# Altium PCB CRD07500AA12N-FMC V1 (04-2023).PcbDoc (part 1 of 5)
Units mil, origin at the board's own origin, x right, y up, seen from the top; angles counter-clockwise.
Board outline 8000 x 8000 mil, 4 copper layers (Top Layer, Layer 1, Layer 2, Bottom Layer), stack 107.988 mil thick; 393 components, 213 nets, 1142 pads, 380 vias.
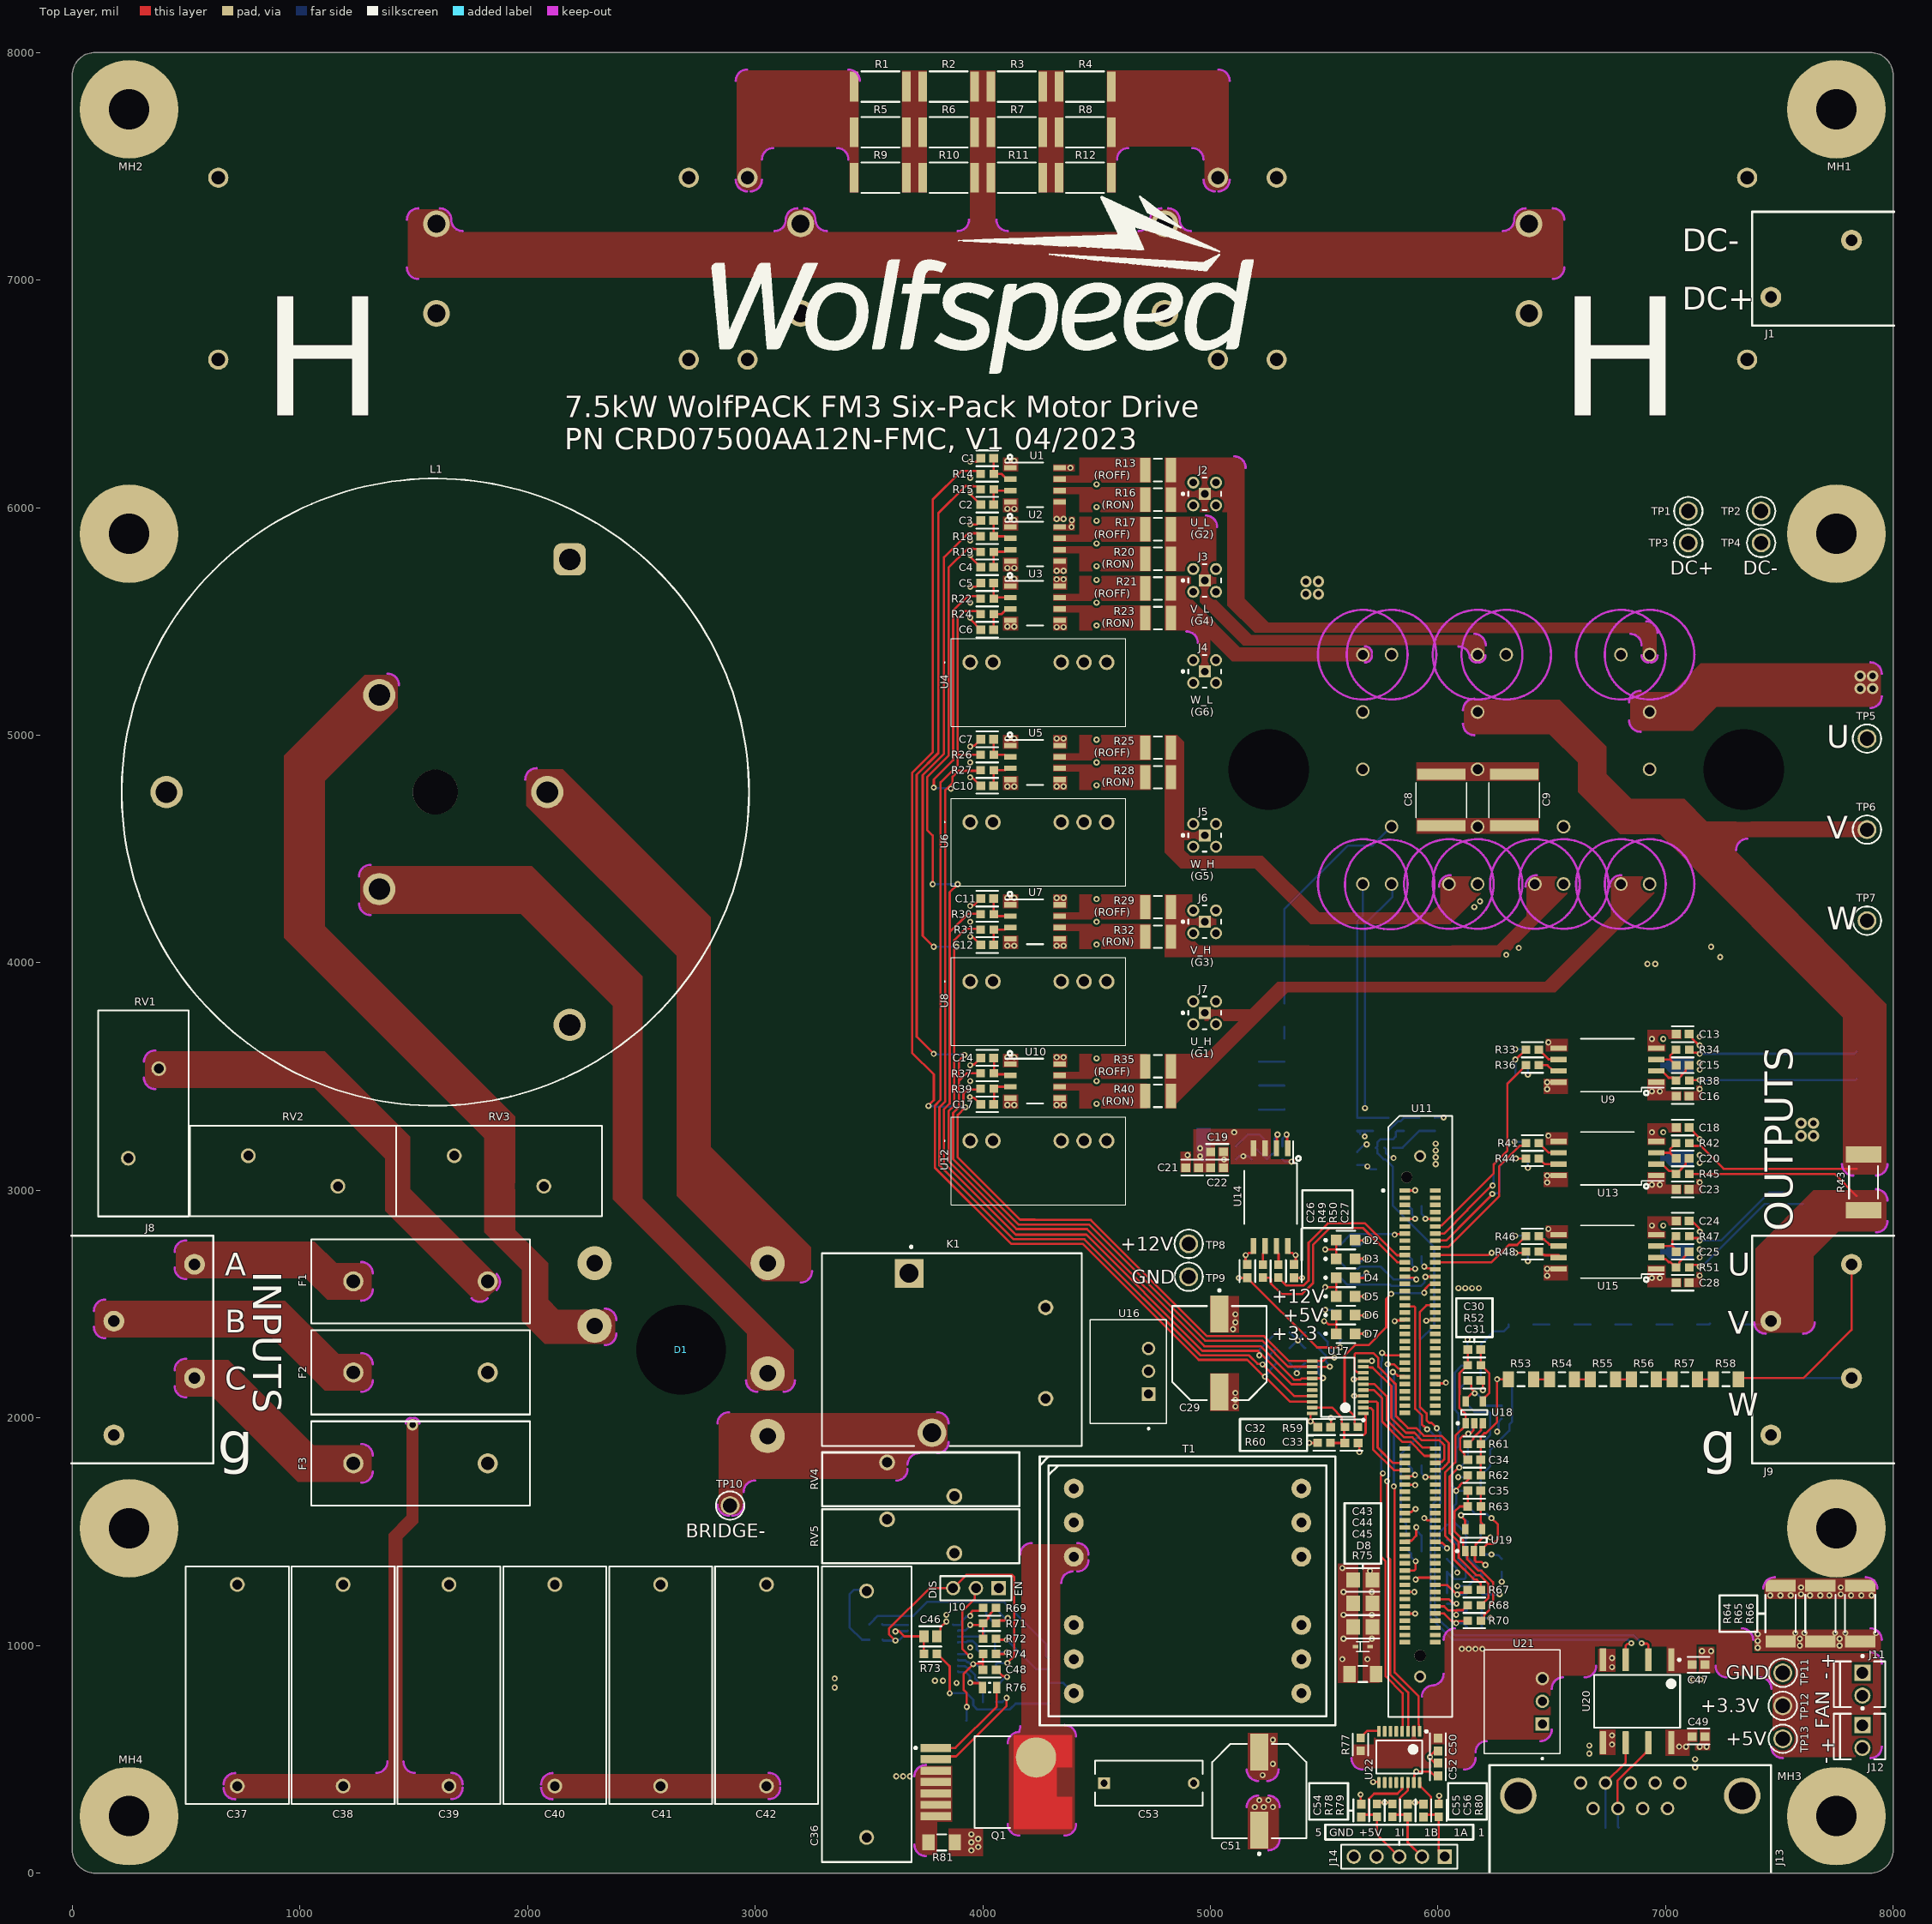
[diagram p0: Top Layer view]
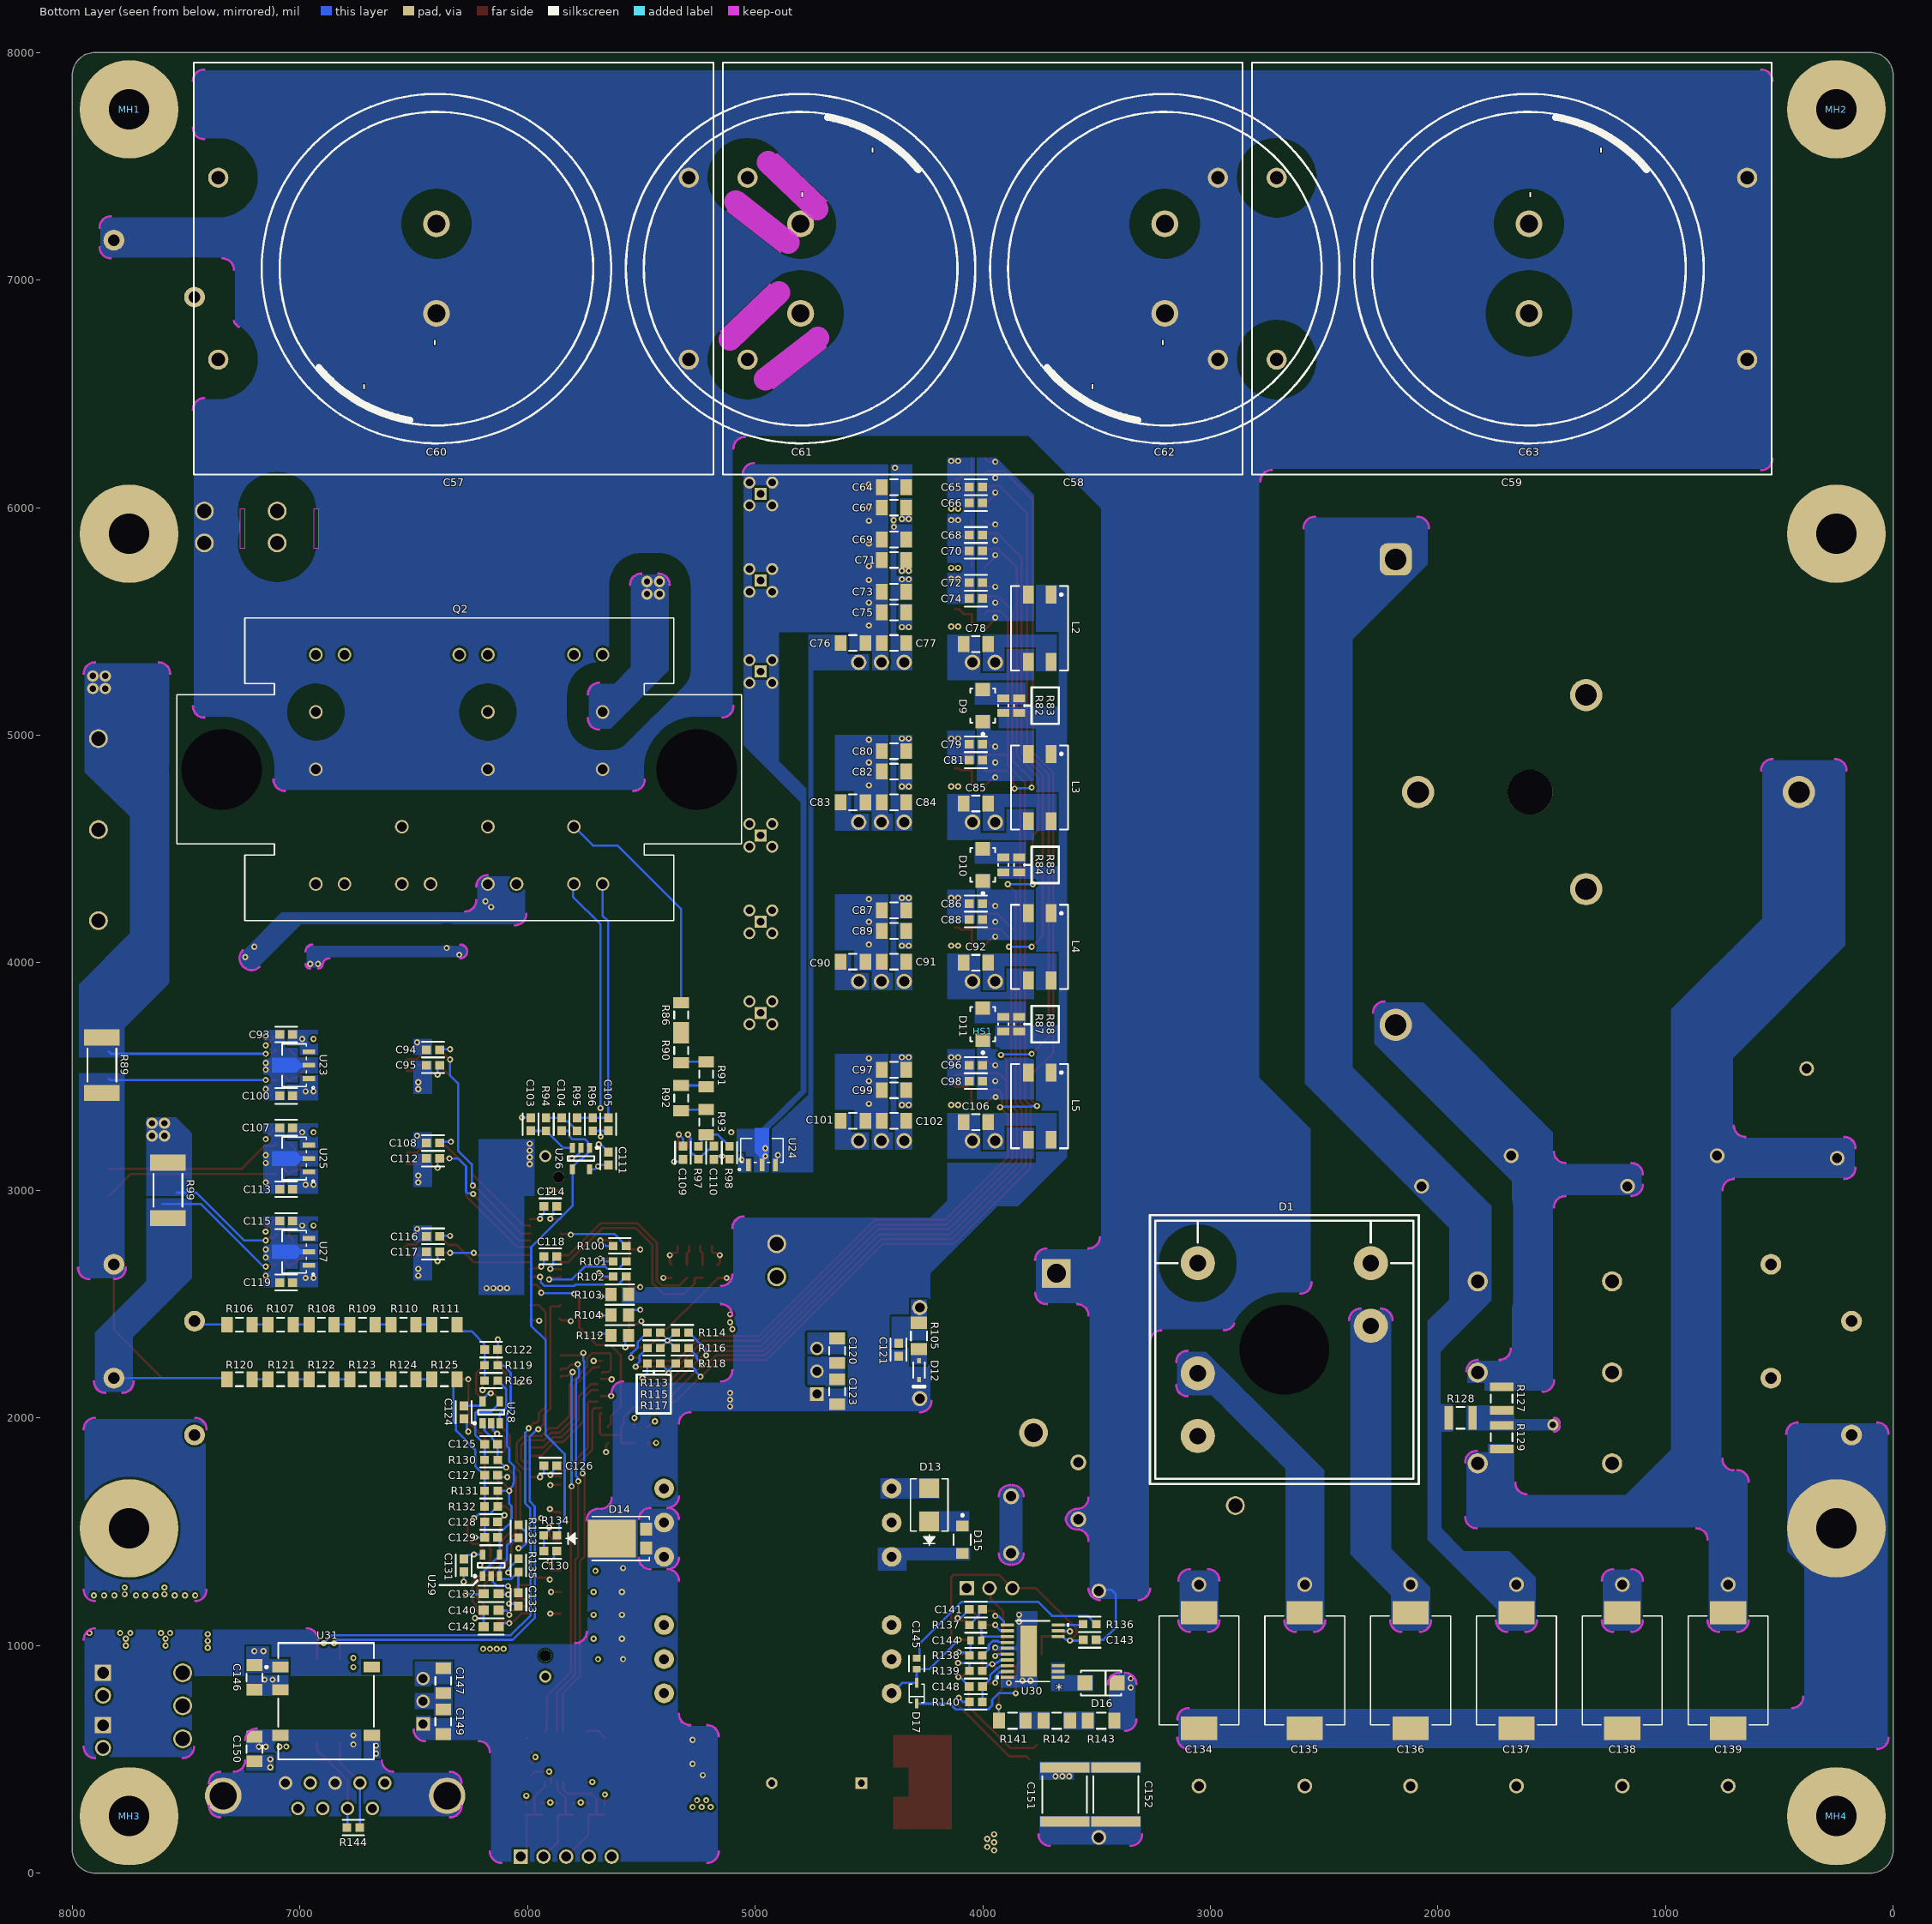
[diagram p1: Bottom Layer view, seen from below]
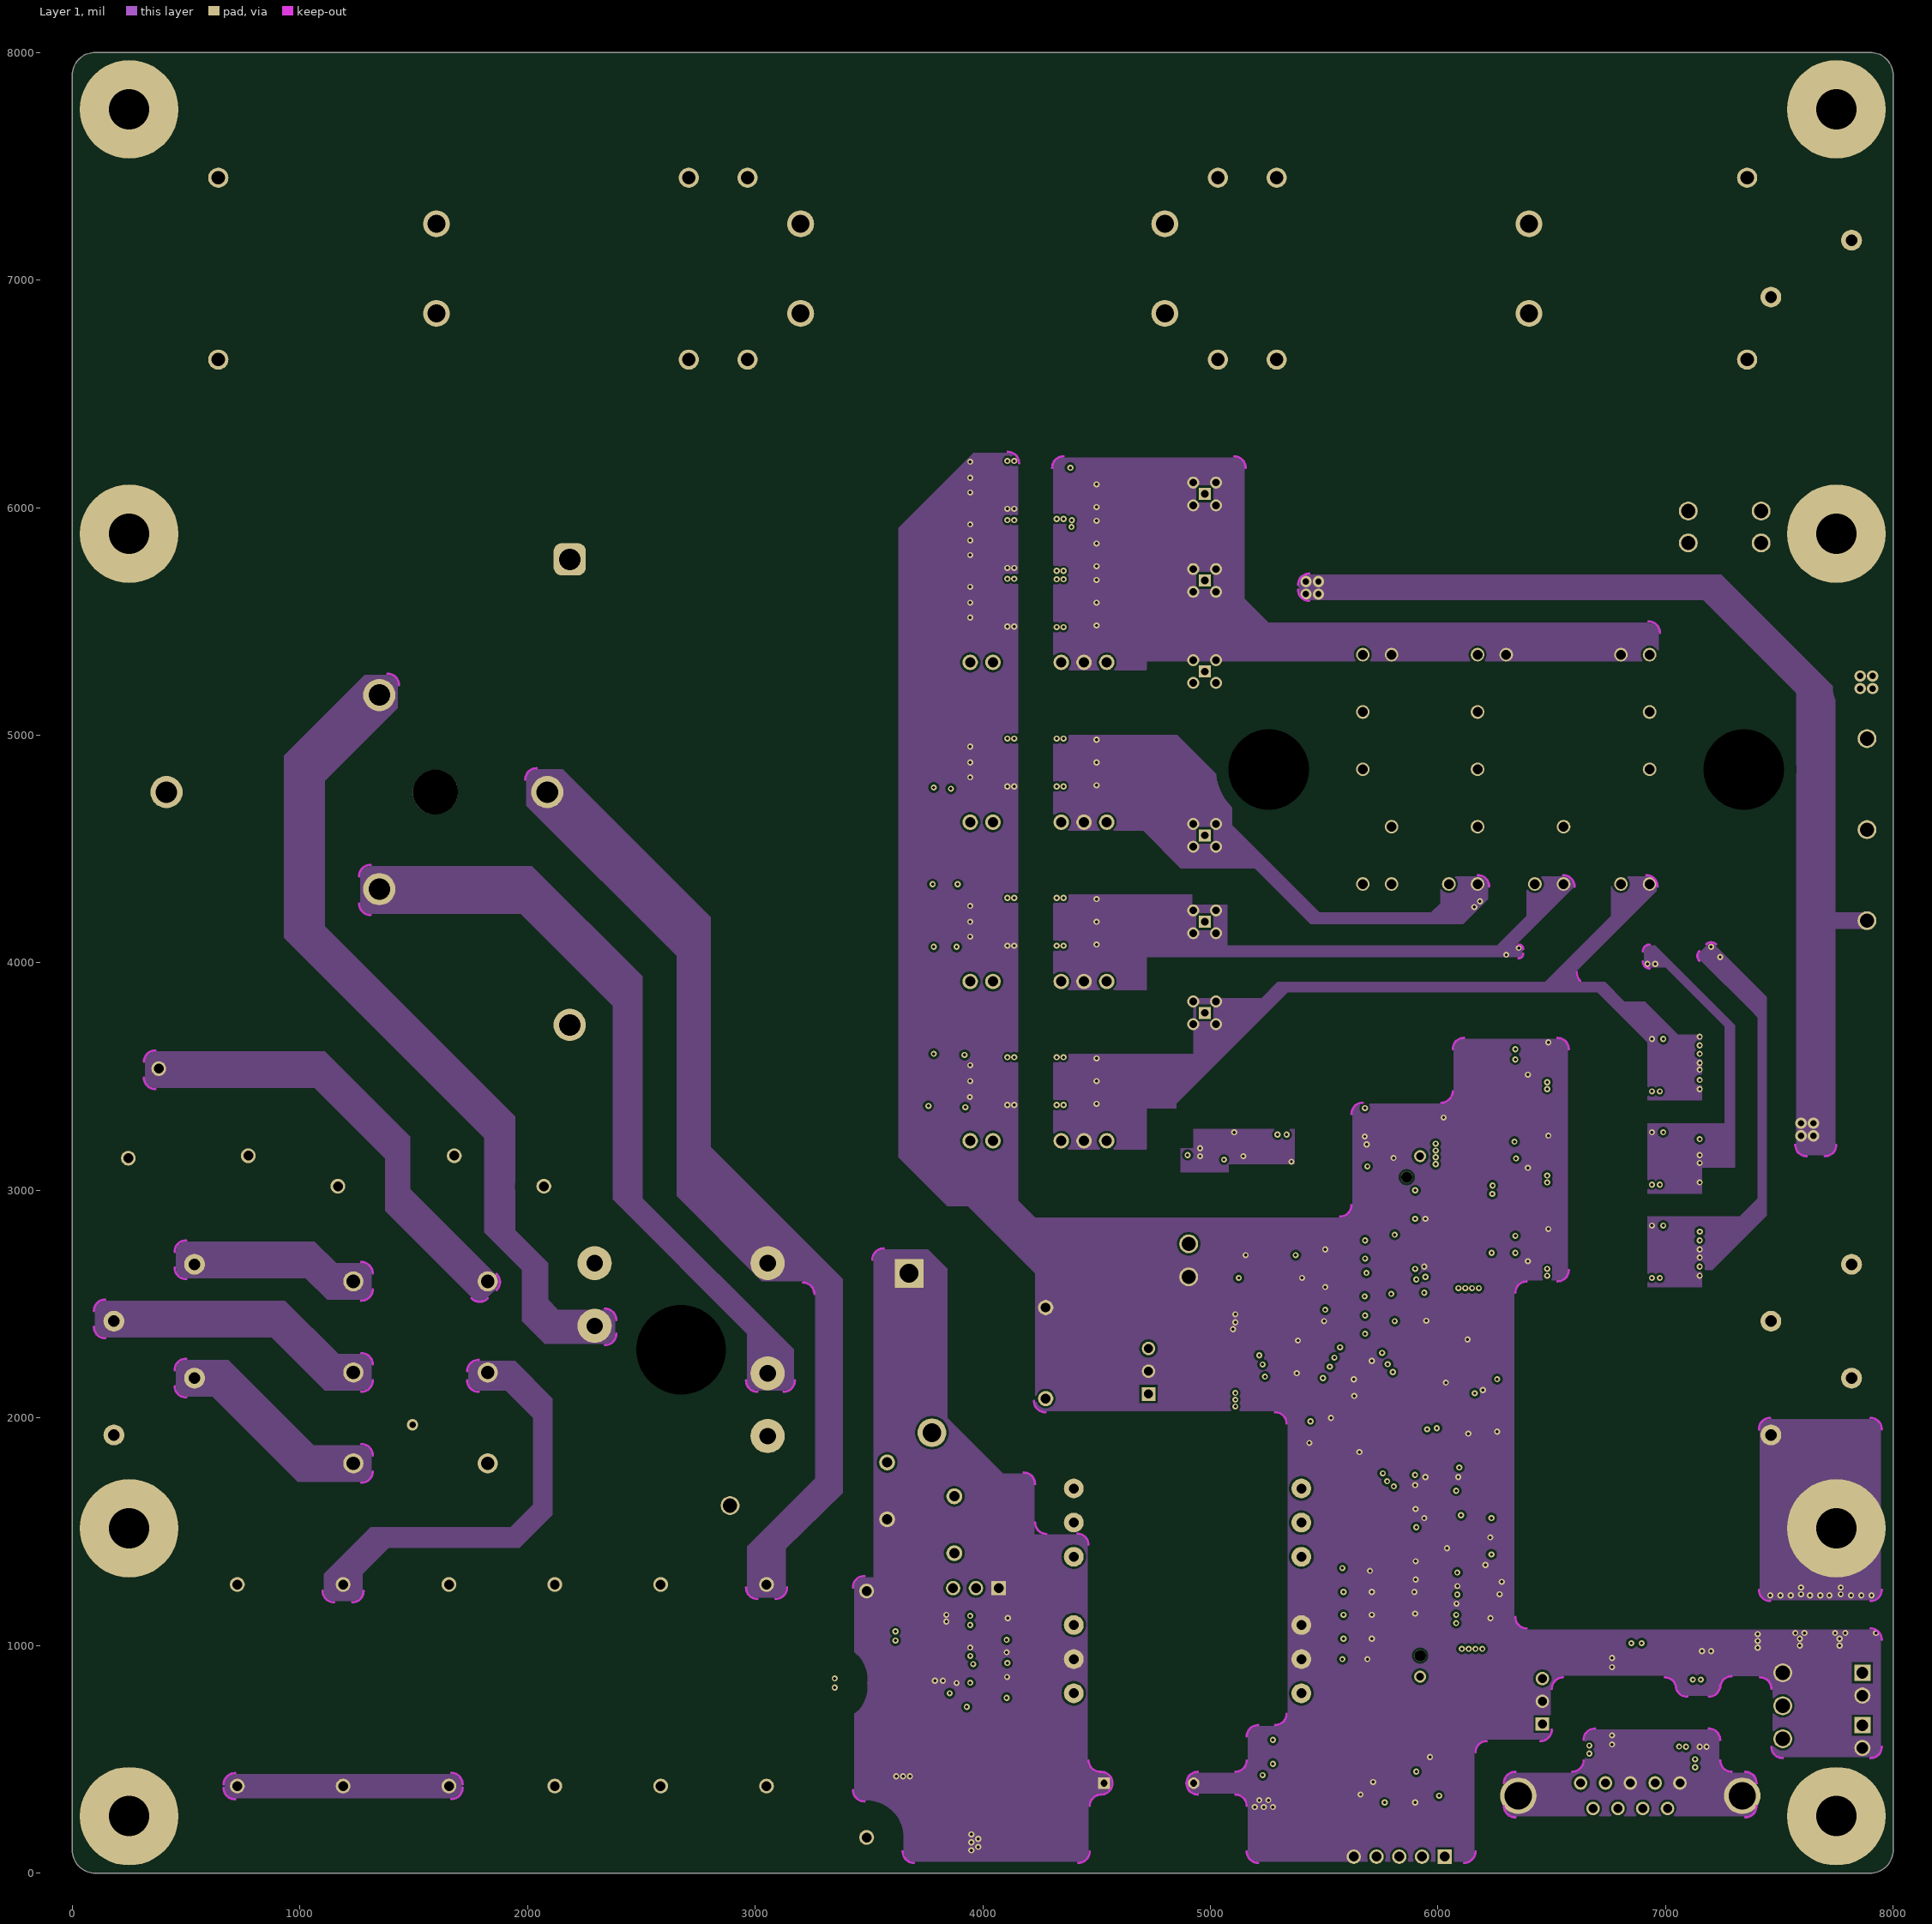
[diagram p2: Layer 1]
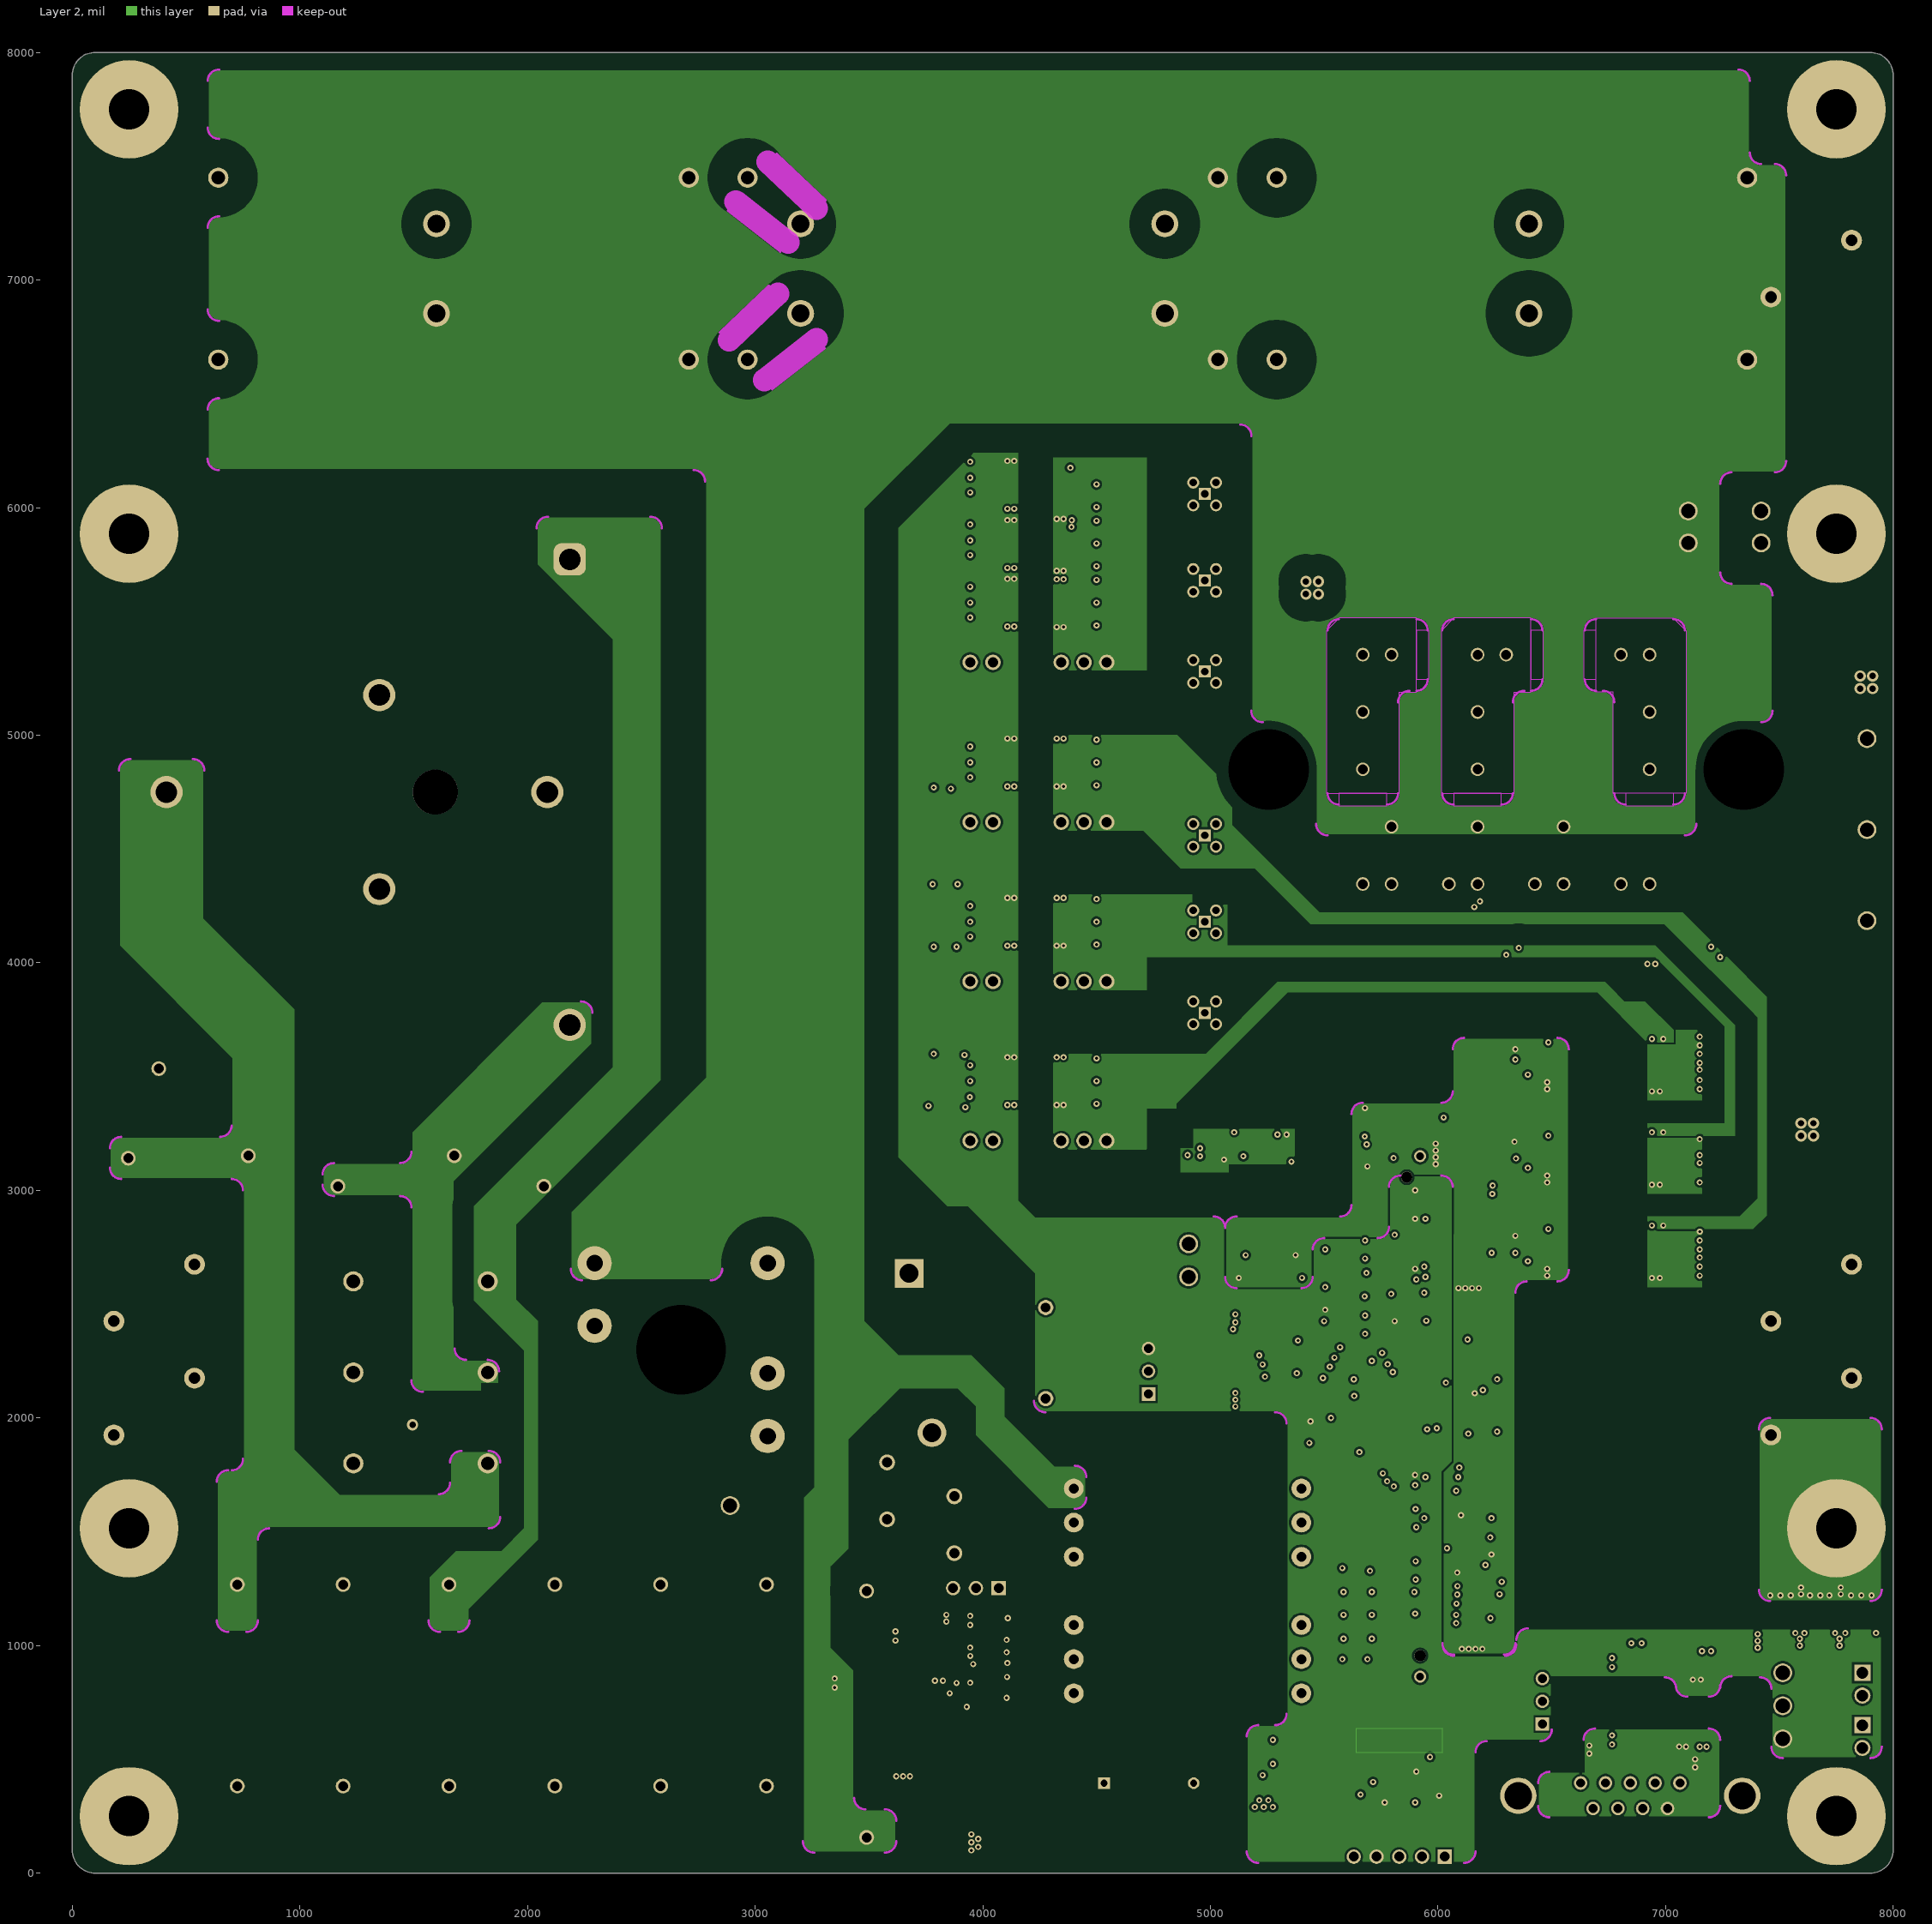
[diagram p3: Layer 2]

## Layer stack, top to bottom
Top Solder: solder mask 0.4, Solder Resist, Dk 3.5
Top Layer: signal copper 2.756
Dielectric 2: prepreg 7.894, PP-006, Dk 4.1
Layer 1: signal copper 1.378
Dielectric 1: dielectric 83.932, FR-4, Dk 4.8
Layer 2: signal copper 1.378
Dielectric 3: prepreg 7.894, PP-006, Dk 4.1
Bottom Layer: signal copper 2.756
Bottom Solder: solder mask 0.4, Solder Resist, Dk 3.5

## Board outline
0,100 0,7900 cw(c100,7900) 100,8000 7900,8000 cw(c7900,7900) 8000,7900 8000,100 cw(c7900,100) 7900,0 100,0 cw(c100,100)

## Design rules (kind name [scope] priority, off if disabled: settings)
Clearance Keepout [IsKeepOut] p1: gap=0 ignorepadtopadclearanceinfootprint=FALSE
Clearance DC+_HOLE [InNetClass('DC+') vs HoleDiameter > 180] p2: gap=35 ignorepadtopadclearanceinfootprint=FALSE except(0: Arc-Hole Track-Hole SMDPad-Hole THPad-Hole Via-Hole Fill-Hole Poly-Hole Region-Hole Text-Hole)
Clearance Hole [HoleDiameter > 180] p3: gap=55 ignorepadtopadclearanceinfootprint=FALSE except(0: Arc-Hole Track-Hole SMDPad-Hole THPad-Hole Via-Hole Fill-Hole Poly-Hole Region-Hole Text-Hole)
Clearance MID [InNet('DC+') OR InNet('DC-') vs InNet('MID')] p4: gap=95 ignorepadtopadclearanceinfootprint=FALSE except(0: Arc-Hole Track-Hole SMDPad-Hole THPad-Hole Via-Hole Fill-Hole Poly-Hole Region-Hole Text-Hole)
Clearance DC+_FB [InNetClass('DC+_FB') vs InNetClass('DC+_FB')] p5: gap=35 ignorepadtopadclearanceinfootprint=FALSE except(0: Arc-Hole Track-Hole SMDPad-Hole THPad-Hole Via-Hole Fill-Hole Poly-Hole Region-Hole Text-Hole)
Clearance U_FB [InNetClass('U_FB') vs InNetClass('U_FB')] p6: gap=35 ignorepadtopadclearanceinfootprint=FALSE except(0: Arc-Hole Track-Hole SMDPad-Hole THPad-Hole Via-Hole Fill-Hole Poly-Hole Region-Hole Text-Hole)
Clearance V_FB [InNetClass('V_FB') vs InNetClass('V_FB')] p7: gap=35 ignorepadtopadclearanceinfootprint=FALSE except(0: Arc-Hole Track-Hole SMDPad-Hole THPad-Hole Via-Hole Fill-Hole Poly-Hole Region-Hole Text-Hole)
Clearance W_FB [InNetClass('W_FB') vs InNetClass('W_FB')] p8: gap=35 ignorepadtopadclearanceinfootprint=FALSE except(0: Arc-Hole Track-Hole SMDPad-Hole THPad-Hole Via-Hole Fill-Hole Poly-Hole Region-Hole Text-Hole)
Clearance W [InNetClass('W') vs NOT InNetClass('W')] p9: gap=95 ignorepadtopadclearanceinfootprint=FALSE except(0: Arc-Hole Track-Hole SMDPad-Hole THPad-Hole Via-Hole Fill-Hole Poly-Hole Region-Hole Text-Hole)
Clearance U [InNetClass('U') vs NOT InNetClass('U')] p10: gap=95 ignorepadtopadclearanceinfootprint=FALSE except(0: Arc-Hole Track-Hole SMDPad-Hole THPad-Hole Via-Hole Fill-Hole Poly-Hole Region-Hole Text-Hole)
Clearance V [InNetClass('V') vs NOT InNetClass('V')] p11: gap=95 ignorepadtopadclearanceinfootprint=FALSE except(0: Arc-Hole Track-Hole SMDPad-Hole THPad-Hole Via-Hole Fill-Hole Poly-Hole Region-Hole Text-Hole)
Clearance XFMR_COP [InNetClass('DC+') vs HasPad('T*-2')] p12: gap=20 ignorepadtopadclearanceinfootprint=FALSE except(0: Arc-Hole Track-Hole SMDPad-Hole THPad-Hole Via-Hole Fill-Hole Poly-Hole Region-Hole Text-Hole)
Clearance XFMR_PIN [HasPad('T*-1') vs HasPad('T*-2')] p13: gap=20 ignorepadtopadclearanceinfootprint=FALSE except(0: Arc-Hole Track-Hole SMDPad-Hole THPad-Hole Via-Hole Fill-Hole Poly-Hole Region-Hole Text-Hole)
Clearance DIODE_PIN [HasPad('D1-4') vs HasPad('D1-3')] p14: gap=130 ignorepadtopadclearanceinfootprint=FALSE except(0: Arc-Hole Track-Hole SMDPad-Hole THPad-Hole Via-Hole Fill-Hole Poly-Hole Region-Hole Text-Hole; 125: THPad-THPad)
Clearance NEUTRAL [InNet('N_X_I') vs InNetClass('AC')] p15: gap=60 ignorepadtopadclearanceinfootprint=FALSE except(0: Arc-Hole Track-Hole SMDPad-Hole THPad-Hole Via-Hole Fill-Hole Poly-Hole Region-Hole Text-Hole)
Clearance DC+ [InNetClass('DC+')] p16: gap=130 ignorepadtopadclearanceinfootprint=FALSE except(0: Arc-Hole Track-Hole SMDPad-Hole THPad-Hole Via-Hole Fill-Hole Poly-Hole Region-Hole Text-Hole)
Clearance AC [InNetClass('AC')] p17: gap=95 ignorepadtopadclearanceinfootprint=FALSE except(0: Arc-Hole Track-Hole SMDPad-Hole THPad-Hole Via-Hole Fill-Hole Poly-Hole Region-Hole Text-Hole)
Clearance Default [All] p18: gap=10 ignorepadtopadclearanceinfootprint=FALSE except(0: Arc-Hole Track-Hole SMDPad-Hole THPad-Hole Via-Hole Fill-Hole Poly-Hole Region-Hole Text-Hole; 6: SMDPad-SMDPad THPad-THPad)
Height [All] p1: minheight=0 maxheight=8000 prefheight=500
HoleSize [All] p1: absolutevalues=TRUE maxlimit=400 minlimit=1 maxpercent=80.000 minpercent=20.000
MinimumSolderMaskSliver [All] p1: minsoldermaskwidth=1.5
PolygonConnect [All] p1: connectstyle=Direct reliefconductorwidth=10 reliefentries=4 polygonreliefangle="90 Angle" airgapwidth=10
RoutingVias [All] p1: holewidth=28 width=50 viastyle="Through Hole" minholewidth=28 minwidth=50 maxholewidth=28 maxwidth=50
SilkToSilkClearance [All] p1: silktosilkclearance=4
SilkToSolderMaskClearance [IsPad] p1: minsilkscreentomaskgap=2 clearancetoexposedcopper=TRUE
SolderMaskExpansion [All] p1: expansion=4 istentingtop=FALSE
Width Encoder [All] p1: maxlimit=10 minlimit=6 preferedwidth=10 midlayer1_minwidth=10 midlayer2_minwidth=10 bottomlayer_minwidth=10 minimp=50.000000 maximp=50.000000 favimp=50.000000
Width [All] p2: maxlimit=10 minlimit=10 preferedwidth=10
25 further rules are at their usual default settings.

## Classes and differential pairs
net class Encoder: EQEP1A_3V3 EQEP1B_3V3 EQEP1I_3V3
net class AC_MID: A_FUSE B_FUSE C_FUSE N_X_I
net class DC+_FB: DC+ DC+0 DC+1 DC+2 DC+3 DC+4 DC+_D FLY+0 FLY+1 FLY_IN
net class U_FB: U0 U1 U2 U3 U4 U_OUT
net class W_FB: W0 W1 W2 W3 W4 W_OUT
net class V_FB: V0 V1 V2 V3 V4 V_OUT
net class W: +5V_W_HS +15V_W_HS -3V_W_HS AINN_W AINP_W G5 G5H G5L S5 W W_OUT
net class V: +5V_V_HS +15V_V_HS -3V_V_HS AINN_V AINP_V G3 G3H G3L S3 V V_OUT
net class U: +5V_U_HS +15V_U_HS -3V_U_HS AINN_U AINP_U G1 G1H G1L S1 U U_OUT
net class AC: A A_FILT A_FUSE B B_FILT B_FUSE C C_FILT C_FUSE
net class DC-: DC- FLY_S G2 G2H G2L G4 G4H G4L G6 G6H G6L SL
net class DC+: DC+
component class "06 - Auxiliary Power": C21 C22 C29 C36 C43 C44 C45 C46 C48 C51 C53 C93 C100 C107 C113 C115 C119 C120 C123 C129 C131 C133 C141 C143 C144 C145 C146 C147 C148 C149 C150 C151 C152 D5 D6 D7 D8 D9 D10 D11 D13 D14 D15 D16 D17 J10 J11 J12 Q1 R69 R71 R72 R73 R74 R75 R76 R81 R82 R83 R84 R85 R87 R88 R103 R104 R112 R133 R135 R136 R137 R138 R139 R140 R141 R142 R143 T1 U16 U21 U23 U24 U25 U27 U29 U30 U31
component class "05 - Sense": C13 C15 C16 C18 C19 C20 C23 C24 C25 C26 C27 C28 C30 C31 C34 C35 C94 C95 C108 C109 C110 C112 C116 C117 C122 C124 C125 C127 C128 C132 C140 C142 R33 R34 R36 R38 R41 R42 R44 R45 R46 R47 R48 R49 R50 R51 R52 R53 R54 R55 R56 R57 R58 R61 R62 R63 R67 R68 R70 R86 R90 R91 R92 R93 R97 R98 R106 R107 R108 R109 R110 R111 R119 R120 R121 R122 R123 R124 R125 R126 R130 R131 R132 U9 U13 U14 U15 U18 U19 U28
component class "03 - Controller": C47 C49 C50 C52 C54 C55 C56 C114 C118 C126 D2 D3 D4 J13 J14 R77 R78 R79 R80 R100 R101 R102 R144 TP8 TP9 TP11 TP12 TP13 U11 U20 U22
component class "04 - Gate Drivers": C1 C2 C3 C4 C5 C6 C7 C10 C11 C12 C14 C17 C32 C33 C64 C65 C66 C67 C68 C69 C70 C71 C72 C73 C74 C75 C76 C77 C78 C79 C80 C81 C82 C83 C84 C85 C86 C87 C88 C89 C90 C91 C92 C96 C97 C98 C99 C101 C102 C103 C104 C105 C106 C111 C130 L2 L3 L4 L5 R13 R14 R15 R16 R17 R18 R19 R20 R21 R22 R23 R24 R25 R26 R27 R28 R29 R30 R31 R32 R35 R37 R39 R40 R59 R60 R94 R95 R96 R113 R114 R115 R116 R117 R118 R134 U1 U2 U3 U4 U5 U6 U7 U8 U10 U12 U17 U26
component class "02 - Power Stage": C8 C9 C37 C38 C39 C40 C41 C42 C57 C58 C59 C60 C61 C62 C63 C121 C134 C135 C136 C137 C138 C139 D1 D12 F1 F2 F3 HS1 J1 J2 J3 J4 J5 J6 J7 J8 J9 K1 L1 MH1 MH2 MH3 MH4 Q2 R1 R2 R3 R4 R5 R6 R7 R8 R9 R10 R11 R12 R43 R64 R65 R66 R89 R99 R105 R127 R128 R129 RV1 RV2 RV3 RV4 RV5 TP1 TP2 TP3 TP4 TP5 TP6 TP7 TP10

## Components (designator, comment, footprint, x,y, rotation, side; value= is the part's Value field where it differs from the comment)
C1 "CL10C560JB8NNNC" FP-C0603C-CF-IPC_B 4020,6217 r180 top value=56pF
C2 "CL10C560JB8NNNC" FP-C0603C-CF-IPC_B 4020,6013 r180 top value=56pF
C3 "CL10C560JB8NNNC" FP-C0603C-CF-IPC_B 4020,5943 r180 top value=56pF
C4 "CL10C560JB8NNNC" FP-C0603C-CF-IPC_B 4020,5738 r180 top value=56pF
C5 "CL10C560JB8NNNC" FP-C0603C-CF-IPC_B 4020,5668 r180 top value=56pF
C6 "CL10C560JB8NNNC" FP-C0603C-CF-IPC_B 4020,5464 r180 top value=56pF
C7 "CL10C560JB8NNNC" FP-C0603C-CF-IPC_B 4020,4982 r180 top value=56pF
C8 "LDEQD1220KA5N00" CAP_LDE_QD_1220_KEM 6015,4715 r90 top value=2.2nF
C9 "LDEQD1220KA5N00" CAP_LDE_QD_1220_KEM 6335,4715 r90 top value=2.2nF
C10 "CL10C560JB8NNNC" FP-C0603C-CF-IPC_B 4020,4778 r180 top value=56pF
C11 "CL10C560JB8NNNC" FP-C0603C-CF-IPC_B 4020,4282 r180 top value=56pF
C12 "CL10C560JB8NNNC" FP-C0603C-CF-IPC_B 4020,4078 r180 top value=56pF
C13 "CL10A475MA8NQNC" FP-C0603C-CF-IPC_B 7075,3686 r180 top value=4.7µF
C14 "CL10C560JB8NNNC" FP-C0603C-CF-IPC_B 4020,3582 r180 top value=56pF
C15 "C0603C472K3RAC7867" FP-C0603C-CF-IPC_B 7075,3550 r180 top value=4.7nF
C16 "C0603C104K3RACTU" FP-C0603C-CF-IPC_B 7075,3414 r0 top value=0.10μF
C17 "CL10C560JB8NNNC" FP-C0603C-CF-IPC_B 4020,3378 r180 top value=56pF
C18 "CL10A475MA8NQNC" FP-C0603C-CF-IPC_B 7075,3276 r180 top value=4.7µF
C19 "CL10A475MA8NQNC" FP-C0603C-CF-IPC_B 5030,3169 r180 top value=4.7µF
C20 "C0603C472K3RAC7867" FP-C0603C-CF-IPC_B 7075,3140 r180 top value=4.7nF
C21 "C1608X7R1H334K080AC" FP-C0603C-CF-IPC_B 4920,3100 r0 top value=330nF
C22 "C0603C104K3RACTU" FP-C0603C-CF-IPC_B 5030,3100 r180 top value=0.10μF
C23 "C0603C104K3RACTU" FP-C0603C-CF-IPC_B 7075,3004 r0 top value=0.10μF
C24 "CL10A475MA8NQNC" FP-C0603C-CF-IPC_B 7075,2866 r180 top value=4.7µF
C25 "C0603C472K3RAC7867" FP-C0603C-CF-IPC_B 7075,2730 r180 top value=4.7nF
C26 "CL10A475MA8NQNC" FP-C0603C-CF-IPC_B 5163,2645 r90 top value=4.7µF
C27 "C0603C104K3RACTU" FP-C0603C-CF-IPC_B 5367,2645 r270 top value=0.10μF
C28 "C0603C104K3RACTU" FP-C0603C-CF-IPC_B 7075,2594 r0 top value=0.10μF
C29 "EEHZK1E471P" FP-EEH-G-MFG 5040,2285 r270 top value=470μF
C30 "CL10B103KA8WPNC" FP-C0603C-CF-IPC_B 6160,2300 r180 top value=10nF
C31 "C0603C104K3RACTU" FP-C0603C-CF-IPC_B 6160,2164 r0 top value=0.10μF
C32 "GRT188R61H225ME13D" FP-C0603C-CF-IPC_B 5500,1960 r0 top value=2.2μF
C33 "CL10C560JB8NNNC" FP-C0603C-CF-IPC_B 5620,1890 r0 top value=56pF
C34 "CL10B103KA8WPNC" FP-C0603C-CF-IPC_B 6160,1816 r180 top value=10nF
C35 "CL10B103KA8WPNC" FP-C0603C-CF-IPC_B 6160,1680 r180 top value=10nF
C36 "890724427001CS" WCAP-FTDB_L32W9H18 3490,698 r90 top locked value=1µF
C37 "890334026027CS" WCAP-FTXX_L26W11H20_CS 725,825 r270 top value=1µF
C38 "890334026027CS" WCAP-FTXX_L26W11H20_CS 1190,825 r270 top value=1µF
C39 "890334026027CS" WCAP-FTXX_L26W11H20_CS 1655,825 r270 top value=1µF
C40 "890334026027CS" WCAP-FTXX_L26W11H20_CS 2120,825 r270 top value=1µF
C41 "890334026027CS" WCAP-FTXX_L26W11H20_CS 2585,825 r270 top value=1µF
C42 "890334026027CS" WCAP-FTXX_L26W11H20_CS 3050,825 r270 top value=1µF
C43 "C3216JB1E336M160AC" FP-C3216-160-0_2-IPC_C 5670,1288 r0 top value=33μF
C44 "C3216JB1E336M160AC" FP-C3216-160-0_2-IPC_C 5670,1185 r0 top value=33μF
C45 "C3216JB1E336M160AC" FP-C3216-160-0_2-IPC_C 5670,1082 r0 top value=33μF
C46 "CL21A475KBQNNNE" FP-CL21-IPC_C 3770,1040 r0 top value=4.7μF
C47 "C0603C104K3RACTU" FP-C0603C-CF-IPC_B 7145,915 r0 top value=0.10μF
C48 "C0603C102J1GACTU" FP-C0603C-CF-IPC_B 4030,894 r180 top value=1nF
C49 "C0603C104K3RACTU" FP-C0603C-CF-IPC_B 7145,600 r0 top value=0.10μF
C50 "C0603C104K3RACTU" FP-C0603C-CF-IPC_B 6000,565 r270 top value=0.10μF
C51 "EEHZK1E471P" FP-EEH-G-MFG 5215,360 r90 top value=470μF
C52 "C0603C104K3RACTU" FP-C0603C-CF-IPC_B 6000,455 r90 top value=0.10μF
C53 "VY1222M47Y5UQ6TV0" FP-VY1470-MFG 4730,395 r0 top value=2.2nF
C54 "C0603C102J1GACTU" FP-C0603C-CF-IPC_B 5663,275 r90 top value=1nF
C55 "C0603C102J1GACTU" FP-C0603C-CF-IPC_B 5867,275 r90 top value=1nF
C56 "C0603C102J1GACTU" FP-C0603C-CF-IPC_B 5936,275 r90 top value=1nF
C57 "75µF, 900V" WCAP-FTDB_L57W45H65 6325,7050 r180 bottom locked value=75µF
C58 "75µF, 900V" WCAP-FTDB_L57W45H65 4000,7050 r180 bottom locked value=75µF
C59 "75µF, 900V" WCAP-FTDB_L57W45H65 1675,7050 r180 bottom locked value=75µF
C60 "B43630A9128M000" B43630A9128M000 6400,7050 r270 bottom locked value=1.2mF
C61 "B43630A9128M000" B43630A9128M000 4800,7050 r90 bottom locked value=1.2mF
C62 "B43630A9128M000" B43630A9128M000 3200,7050 r270 bottom locked value=1.2mF
C63 "B43630A9128M000" B43630A9128M000 1600,7050 r90 bottom locked value=1.2mF
C64 "CL31B106KAHSFNE" FP-CL31-IPC_B 4390,6090 r180 bottom value=10μF
C65 "GRT188R61H225ME13D" FP-C0603C-CF-IPC_B 4030,6090 r180 bottom value=2.2μF
C66 "GRT188R61H225ME13D" FP-C0603C-CF-IPC_B 4030,6020 r180 bottom value=2.2μF
C67 "CL31B106KAHSFNE" FP-CL31-IPC_B 4390,6000 r0 bottom value=10μF
C68 "GRT188R61H225ME13D" FP-C0603C-CF-IPC_B 4030,5880 r180 bottom value=2.2μF
C69 "CL31B106KAHSFNE" FP-CL31-IPC_B 4390,5860 r180 bottom value=10μF
C70 "GRT188R61H225ME13D" FP-C0603C-CF-IPC_B 4030,5810 r180 bottom value=2.2μF
C71 "CL31B106KAHSFNE" FP-CL31-IPC_B 4390,5770 r0 bottom value=10μF
C72 "GRT188R61H225ME13D" FP-C0603C-CF-IPC_B 4030,5670 r180 bottom value=2.2μF
C73 "CL31B106KAHSFNE" FP-CL31-IPC_B 4390,5630 r180 bottom value=10μF
C74 "GRT188R61H225ME13D" FP-C0603C-CF-IPC_B 4030,5600 r180 bottom value=2.2μF
C75 "CL31B106KAHSFNE" FP-CL31-IPC_B 4390,5540 r0 bottom value=10μF
C76 "CL31B106KAHSFNE" FP-CL31-IPC_B 4570,5405 r180 bottom value=10μF
C77 "CL31B106KAHSFNE" FP-CL31-IPC_B 4390,5405 r180 bottom value=10μF
C78 "CL31B106KAHSFNE" FP-CL31-IPC_B 4030,5400 r0 bottom value=10μF
C79 "GRT188R61H225ME13D" FP-C0603C-CF-IPC_B 4030,4960 r180 bottom value=2.2μF
C80 "CL31B106KAHSFNE" FP-CL31-IPC_B 4390,4930 r180 bottom value=10μF
C81 "GRT188R61H225ME13D" FP-C0603C-CF-IPC_B 4030,4890 r180 bottom value=2.2μF
C82 "CL31B106KAHSFNE" FP-CL31-IPC_B 4390,4840 r0 bottom value=10μF
C83 "CL31B106KAHSFNE" FP-CL31-IPC_B 4570,4705 r180 bottom value=10μF
C84 "CL31B106KAHSFNE" FP-CL31-IPC_B 4390,4705 r180 bottom value=10μF
C85 "CL31B106KAHSFNE" FP-CL31-IPC_B 4030,4700 r0 bottom value=10μF
C86 "GRT188R61H225ME13D" FP-C0603C-CF-IPC_B 4030,4260 r180 bottom value=2.2μF
C87 "CL31B106KAHSFNE" FP-CL31-IPC_B 4390,4230 r180 bottom value=10μF
C88 "GRT188R61H225ME13D" FP-C0603C-CF-IPC_B 4030,4190 r180 bottom value=2.2μF
C89 "CL31B106KAHSFNE" FP-CL31-IPC_B 4390,4140 r0 bottom value=10μF
C90 "CL31B106KAHSFNE" FP-CL31-IPC_B 4570,4005 r180 bottom value=10μF
C91 "CL31B106KAHSFNE" FP-CL31-IPC_B 4390,4005 r180 bottom value=10μF
C92 "CL31B106KAHSFNE" FP-CL31-IPC_B 4030,4000 r0 bottom value=10μF
C93 "C1608X7R1H334K080AC" FP-C0603C-CF-IPC_B 7060,3685 r0 bottom value=330nF
C94 "CL10A475MA8NQNC" FP-C0603C-CF-IPC_B 6415,3618 r0 bottom value=4.7µF
C95 "C0603C104K3RACTU" FP-C0603C-CF-IPC_B 6415,3550 r180 bottom value=0.10μF
C96 "GRT188R61H225ME13D" FP-C0603C-CF-IPC_B 4030,3550 r180 bottom value=2.2μF
C97 "CL31B106KAHSFNE" FP-CL31-IPC_B 4390,3530 r180 bottom value=10μF
C98 "GRT188R61H225ME13D" FP-C0603C-CF-IPC_B 4030,3480 r180 bottom value=2.2μF
C99 "CL31B106KAHSFNE" FP-CL31-IPC_B 4390,3440 r0 bottom value=10μF
C100 "C0603C104K3RACTU" FP-C0603C-CF-IPC_B 7060,3415 r0 bottom value=0.10μF
C101 "CL31B106KAHSFNE" FP-CL31-IPC_B 4570,3305 r180 bottom value=10μF
C102 "CL31B106KAHSFNE" FP-CL31-IPC_B 4390,3305 r180 bottom value=10μF
C103 "C0603C564K8PACTU" FP-C0603C-CF-IPC_B 5986,3290 r90 bottom value=560nF
C104 "C0603C105K8RACTU" FP-C0603C-CF-IPC_B 5850,3290 r90 bottom value=1μF
C105 "C0603C104K3RACTU" FP-C0603C-CF-IPC_B 5645,3290 r270 bottom value=0.10μF
C106 "CL31B106KAHSFNE" FP-CL31-IPC_B 4030,3300 r0 bottom value=10μF
C107 "C1608X7R1H334K080AC" FP-C0603C-CF-IPC_B 7060,3275 r0 bottom value=330nF
C108 "CL10A475MA8NQNC" FP-C0603C-CF-IPC_B 6415,3208 r0 bottom value=4.7µF
C109 "C0603C104K3RACTU" FP-C0603C-CF-IPC_B 5317,3165 r270 bottom value=0.10μF
C110 "C0603C472K3RAC7867" FP-C0603C-CF-IPC_B 5181,3165 r270 bottom value=4.7nF
C111 "C0603C104K3RACTU" FP-C0603C-CF-IPC_B 5645,3140 r90 bottom value=0.10μF
C112 "C0603C104K3RACTU" FP-C0603C-CF-IPC_B 6415,3140 r180 bottom value=0.10μF
C113 "C0603C104K3RACTU" FP-C0603C-CF-IPC_B 7060,3005 r0 bottom value=0.10μF
C114 "C0603C104K3RACTU" FP-C0603C-CF-IPC_B 5900,2930 r0 bottom value=0.10μF
C115 "C1608X7R1H334K080AC" FP-C0603C-CF-IPC_B 7060,2865 r0 bottom value=330nF
C116 "C0603C104K3RACTU" FP-C0603C-CF-IPC_B 6415,2798 r0 bottom value=0.10μF
C117 "CL10A475MA8NQNC" FP-C0603C-CF-IPC_B 6415,2730 r180 bottom value=4.7µF
C118 "C0603C104K3RACTU" FP-C0603C-CF-IPC_B 5900,2710 r0 bottom value=0.10μF
C119 "C0603C104K3RACTU" FP-C0603C-CF-IPC_B 7060,2595 r0 bottom value=0.10μF
C120 "CL31B106KAHSFNE" FP-CL31-IPC_B 4640,2295 r270 bottom value=10μF
C121 "C0603C104K3RACTU" FP-C0603C-CF-IPC_B 4370,2300 r90 bottom value=0.10μF
C122 "CL10B103KA8WPNC" FP-C0603C-CF-IPC_B 6160,2300 r180 bottom value=10nF
C123 "CL31B106KAHSFNE" FP-CL31-IPC_B 4640,2115 r90 bottom value=10μF
C124 "C0603C104K3RACTU" FP-C0603C-CF-IPC_B 6280,2025 r270 bottom value=0.10μF
C125 "CL10B103KA8WPNC" FP-C0603C-CF-IPC_B 6160,1885 r180 bottom value=10nF
C126 "C0603C104K3RACTU" FP-C0603C-CF-IPC_B 5900,1790 r0 bottom value=0.10μF
C127 "CL10B103KA8WPNC" FP-C0603C-CF-IPC_B 6160,1748 r180 bottom value=10nF
C128 "C0603C104K3RACTU" FP-C0603C-CF-IPC_B 6160,1543 r0 bottom value=0.10μF
C129 "C0603C104K3RACTU" FP-C0603C-CF-IPC_B 6160,1475 r0 bottom value=0.10μF
C130 "C0603C472K3RAC7867" FP-C0603C-CF-IPC_B 5900,1415 r180 bottom value=4.7nF
C131 "C0603C104K3RACTU" FP-C0603C-CF-IPC_B 6280,1352 r270 bottom value=0.10μF
C132 "CGA3E2X7R1H222K080AA" FP-GCM188-0_1-IPC_A 6160,1227 r0 bottom value=2.2nF
C133 "C0603C104K3RACTU" FP-C0603C-CF-IPC_B 6040,1202 r270 bottom value=0.10μF
C134 "SMDY1152MY5UCR" CAP_MY5UCR_VIS 3050,890 r270 bottom value=1.5nF
C135 "SMDY1152MY5UCR" CAP_MY5UCR_VIS 2585,890 r270 bottom value=1.5nF
C136 "SMDY1152MY5UCR" CAP_MY5UCR_VIS 2120,890 r270 bottom value=1.5nF
C137 "SMDY1152MY5UCR" CAP_MY5UCR_VIS 1655,890 r270 bottom value=1.5nF
C138 "SMDY1152MY5UCR" CAP_MY5UCR_VIS 1190,890 r270 bottom value=1.5nF
C139 "SMDY1152MY5UCR" CAP_MY5UCR_VIS 725,890 r270 bottom value=1.5nF
C140 "CGA3E2X7R1H222K080AA" FP-GCM188-0_1-IPC_A 6160,1155 r0 bottom value=2.2nF
C141 "C0603C104K3RACTU" FP-C0603C-CF-IPC_B 4030,1158 r0 bottom value=0.10μF
C142 "CGA3E2X7R1H222K080AA" FP-GCM188-0_1-IPC_A 6160,1083 r0 bottom value=2.2nF
C143 "CL10A475MA8NQNC" FP-C0603C-CF-IPC_B 3530,1025 r180 bottom value=4.7µF
C144 "C0603C470K1GACTU" FP-C0603C-CF-MFG 4030,1023 r0 bottom value=47pF
C145 "C0603C470K1GACTU" FP-C0603C-CF-MFG 4290,920 r90 bottom value=47pF
C146 "CL31B106KAHSFNE" FP-CL31-IPC_B 7200,860 r90 bottom value=10μF
C147 "CL31B106KAHSFNE" FP-CL31-IPC_B 6370,845 r270 bottom value=10μF
C148 "C0603C102J1GACTU" FP-C0603C-CF-IPC_B 4030,820 r0 bottom value=1nF
C149 "CL31B106KAHSFNE" FP-CL31-IPC_B 6370,665 r90 bottom value=10μF
C150 "CL31B106KAHSFNE" FP-CL31-IPC_B 7200,545 r90 bottom value=10μF
C151 "C5750X7S3D103K250KA" FP-C5750-250-0_4-IPC_A 3640,345 r90 bottom value=10nF
C152 "C5750X7S3D103K250KA" FP-C5750-250-0_4-IPC_A 3415,345 r90 bottom value=10nF
D1 "SBR2512W" SBR2512W 2675,2300 r270 top locked value=N/A
D2 "LTST-C171GKT" FP-LTST-C171GKT-MFG 5595,2781 r0 top value=GREEN
D3 "LTST-C171KSKT" FP-LTST-C171GKT-MFG-YELLOW 5595,2699 r0 top
D4 "CMD17-21VRD/TR8" FP-LTST-C171GKT-MFG-RED 5595,2616 r0 top value=RED
D5 "LTST-C171GKT" FP-LTST-C171GKT-MFG 5595,2534 r0 top value=GREEN
D6 "LTST-C171GKT" FP-LTST-C171GKT-MFG 5595,2452 r0 top value=GREEN
D7 "LTST-C171GKT" FP-LTST-C171GKT-MFG 5595,2370 r0 top value=GREEN
D8 "CMOZ13V TR PBFREE" DIODE_SOD-523_1P2XP8_CNS 5670,995 r0 top value=N/A
D9 "APTR3216-VFX" FP-APTR3216SECK-MFG 4000,5130 r90 bottom
D10 "APTR3216-VFX" FP-APTR3216SECK-MFG 4000,4430 r90 bottom
D11 "APTR3216-VFX" FP-APTR3216SECK-MFG 4000,3730 r90 bottom
D12 "1N4148WS-7-F" DIOD-SOD323-2-A_V 4280,2210 r270 bottom
D13 "SMBJ188A" SMBJSeries_LTF 4235,1618 r90 bottom value=N/A
D14 "FSV20120V" SOT_20100V_ONS 5590.5,1470 r90 bottom value=N/A
D15 "US1MFA" FP-425AB-MFG 4090,1465 r270 bottom value=N/A
D16 "BZG03C220-M3-08" FP-SMA-MFG 3480,835 r0 bottom value=N/A
D17 "BAV20WS-7-F" SOD323_DIO 4290,790 r90 bottom value=N/A
F1 "696106003002" 696106003002 1530,2600 r0 top value=N/A
F2 "696106003002" 696106003002 1530,2200 r0 top value=N/A
F3 "696106003002" 696106003002 1530,1800 r0 top value=N/A
HS1 "94DN-02000-A-200" 94DN-02000-A-200 4000,3700 r0 bottom locked value=N/A
J1 "1777545" 1777545 7640,7050 r90 top value=N/A
J2 "0734151471" FP-73415-1471-MFG 4975,6060 r0 top value=N/A
J3 "0734151471" FP-73415-1471-MFG 4975,5680 r0 top value=N/A
J4 "0734151471" FP-73415-1471-MFG 4975,5280 r0 top value=N/A
J5 "0734151471" FP-73415-1471-MFG 4975,4560 r0 top value=N/A
J6 "0734151471" FP-73415-1471-MFG 4975,4180 r0 top value=N/A
J7 "0734151471" FP-73415-1471-MFG 4975,3780 r0 top value=N/A
J8 "1777561" 1777561 360,2300 r270 top locked value=N/A
J9 "1777561" 1777561 7640,2300 r90 top locked value=N/A
J10 "61300311121" 61300311121 3970,1252 r180 top value=N/A
J11 "640456-2" TECO-640456-2_V 7865,830 r90 top value=N/A
J12 "640456-2" TECO-640456-2_V 7865,600 r90 top value=N/A
J13 "L717SDE09PA4CH4RC309" L717SDE09PA4CH4RC309 6845,340 r0 top locked value=N/A
J14 "61300511121" 61300511121 5830,72 r180 top value=N/A
K1 "T9GV1L14-12" FP-T9GV1L14-12-MFG 3865,2300 r90 top value=N/A
L1 "47mH" "WE-TPB HV_Type 4XL_744839047160" 1595,4750 r0 top
L2 "744226S" WE-SL2 3750,5470 r270 bottom value=10μH
L3 "744226S" WE-SL2 3750,4770 r270 bottom value=10μH
L4 "744226S" WE-SL2 3750,4070 r270 bottom value=10μH
L5 "744226S" WE-SL2 3750,3370 r270 bottom value=10μH
MH1 "MH_M4_P" MH_M4_P 7750,7750 r180 bottom locked value=N/A
MH2 "MH_M4_P" MH_M4_P 250,7750 r180 bottom locked value=N/A
MH3 "MH_M4_P" MH_M4_P 7750,250 r180 bottom locked value=N/A
MH4 "MH_M4_P" MH_M4_P 250,250 r180 bottom locked value=N/A
Q1 "C3M0280090J" FP-TO-263-7-MFG 4060,400 r270 top value=N/A
Q2 "CCB032M12FM3" FM3_SIX-PACK_3PHASE_CRW 6300,4850 r180 bottom locked value=N/A
R1 "CRGP2512F82K" FP-CRGP2512-IPC_C 3550,7850 r0 top value=82kΩ
R2 "CRGP2512F82K" FP-CRGP2512-IPC_C 3850,7850 r0 top value=82kΩ
R3 "CRGP2512F82K" FP-CRGP2512-IPC_C 4150,7850 r0 top value=82kΩ
R4 "CRGP2512F82K" FP-CRGP2512-IPC_C 4450,7850 r0 top value=82kΩ
R5 "CRGP2512F82K" FP-CRGP2512-IPC_C 3550,7650 r0 top value=82kΩ
R6 "CRGP2512F82K" FP-CRGP2512-IPC_C 3850,7650 r0 top value=82kΩ
R7 "CRGP2512F82K" FP-CRGP2512-IPC_C 4150,7650 r0 top value=82kΩ
R8 "CRGP2512F82K" FP-CRGP2512-IPC_C 4450,7650 r0 top value=82kΩ
R9 "CRGP2512F82K" FP-CRGP2512-IPC_C 3550,7450 r0 top value=82kΩ
R10 "CRGP2512F82K" FP-CRGP2512-IPC_C 3850,7450 r0 top value=82kΩ
R11 "CRGP2512F82K" FP-CRGP2512-IPC_C 4150,7450 r0 top value=82kΩ
R12 "CRGP2512F82K" FP-CRGP2512-IPC_C 4450,7450 r0 top value=82kΩ
R13 "CRCW12100000Z0EAHP" RESC3125X70X40NL20T20 4770,6165 r0 top
R14 "ERJ-3EKF49R9V" FP-MCR03-IPC_B 4020,6148 r0 top value=49.9Ω
R15 "ERJ-3EKF49R9V" FP-MCR03-IPC_B 4020,6081 r0 top value=49.9Ω
R16 "RCWE1210R910FKEA" RESC3125X70X40NL20T20 4770,6035 r0 top value=0.91Ω
R17 "CRCW12100000Z0EAHP" RESC3125X70X40NL20T20 4770,5905 r0 top
R18 "ERJ-3EKF49R9V" FP-MCR03-IPC_B 4020,5874 r0 top value=49.9Ω
R19 "ERJ-3EKF49R9V" FP-MCR03-IPC_B 4020,5806 r0 top value=49.9Ω
R20 "RCWE1210R910FKEA" RESC3125X70X40NL20T20 4770,5775 r0 top value=0.91Ω
R21 "CRCW12100000Z0EAHP" RESC3125X70X40NL20T20 4770,5645 r0 top
R22 "ERJ-3EKF49R9V" FP-MCR03-IPC_B 4020,5600 r0 top value=49.9Ω
R23 "RCWE1210R910FKEA" RESC3125X70X40NL20T20 4770,5515 r0 top value=0.91Ω
R24 "ERJ-3EKF49R9V" FP-MCR03-IPC_B 4020,5532 r0 top value=49.9Ω
R25 "CRCW12100000Z0EAHP" RESC3125X70X40NL20T20 4770,4945 r0 top
R26 "ERJ-3EKF49R9V" FP-MCR03-IPC_B 4020,4914 r0 top value=49.9Ω
R27 "ERJ-3EKF49R9V" FP-MCR03-IPC_B 4020,4846 r0 top value=49.9Ω
R28 "RCWE1210R910FKEA" RESC3125X70X40NL20T20 4770,4815 r0 top value=0.91Ω
R29 "CRCW12100000Z0EAHP" RESC3125X70X40NL20T20 4770,4245 r0 top
R30 "ERJ-3EKF49R9V" FP-MCR03-IPC_B 4020,4214 r0 top value=49.9Ω
R31 "ERJ-3EKF49R9V" FP-MCR03-IPC_B 4020,4146 r0 top value=49.9Ω
R32 "RCWE1210R910FKEA" RESC3125X70X40NL20T20 4770,4115 r0 top value=0.91Ω
R33 "RC0603FR-1322RL" FP-MCR03-IPC_B 6415,3618 r180 top value=22Ω
R34 "RC0603FR-1322RL" FP-MCR03-IPC_B 7075,3618 r180 top value=22Ω
R35 "CRCW12100000Z0EAHP" RESC3125X70X40NL20T20 4770,3545 r0 top
R36 "RC0603FR-1322RL" FP-MCR03-IPC_B 6415,3550 r180 top value=22Ω
R37 "ERJ-3EKF49R9V" FP-MCR03-IPC_B 4020,3514 r0 top value=49.9Ω
R38 "RC0603FR-1322RL" FP-MCR03-IPC_B 7075,3482 r180 top value=22Ω
R39 "ERJ-3EKF49R9V" FP-MCR03-IPC_B 4020,3446 r0 top value=49.9Ω
R40 "RCWE1210R910FKEA" RESC3125X70X40NL20T20 4770,3415 r0 top value=0.91Ω
R41 "RC0603FR-1322RL" FP-MCR03-IPC_B 6415,3208 r180 top value=22Ω
R42 "RC0603FR-1322RL" FP-MCR03-IPC_B 7075,3208 r180 top value=22Ω
R43 "CRE2512-FZ-R002E-3" FP-RC2512-0_65-MFG 7870,3035 r270 top value=2mΩ
R44 "RC0603FR-1322RL" FP-MCR03-IPC_B 6415,3140 r180 top value=22Ω
R45 "RC0603FR-1322RL" FP-MCR03-IPC_B 7075,3072 r180 top value=22Ω
R46 "RC0603FR-1322RL" FP-MCR03-IPC_B 6415,2798 r180 top value=22Ω
R47 "RC0603FR-1322RL" FP-MCR03-IPC_B 7075,2798 r180 top value=22Ω
R48 "RC0603FR-1322RL" FP-MCR03-IPC_B 6415,2730 r180 top value=22Ω
R49 "RC0603FR-1322RL" FP-MCR03-IPC_B 5231,2645 r270 top value=22Ω
R50 "RC0603FR-1322RL" FP-MCR03-IPC_B 5299,2645 r270 top value=22Ω
R51 "RC0603FR-1322RL" FP-MCR03-IPC_B 7075,2662 r180 top value=22Ω
R52 "RC0603FR-070RL" FP-MCR03-IPC_B 6160,2232 r0 top value=0Ω
R53 "TNPW1206249KBEEA" RESC3216X65X50NL15T25 6365,2170 r180 top value=249kΩ
R54 "TNPW1206249KBEEA" RESC3216X65X50NL15T25 6545,2170 r180 top value=249kΩ
R55 "TNPW1206249KBEEA" RESC3216X65X50NL15T25 6725,2170 r180 top value=249kΩ
R56 "TNPW1206249KBEEA" RESC3216X65X50NL15T25 6905,2170 r180 top value=249kΩ
R57 "TNPW1206249KBEEA" RESC3216X65X50NL15T25 7085,2170 r180 top value=249kΩ
R58 "TNPW1206249KBEEA" RESC3216X65X50NL15T25 7265,2170 r180 top value=249kΩ
R59 "ERJ-3EKF49R9V" FP-MCR03-IPC_B 5620,1960 r180 top value=49.9Ω
R60 "ERJ3EKF1002V" FP-MCR03-IPC_B 5500,1890 r0 top value=10kΩ
R61 "RC0603FR-074K99L" FP-MCR03-IPC_B 6160,1885 r180 top value=4.99kΩ
R62 "ERJ-PB3B1801V" FP-MCR03-IPC_B 6160,1748 r180 top value=1.8kΩ
R63 "RC0603FR-070RL" FP-MCR03-IPC_B 6160,1611 r0 top value=0Ω
R64 "RC2512JK-070RL" FP-RC2512-0_65-IPC_A 7505,1140 r270 top value=0Ω
R65 "RC2512JK-070RL" FP-RC2512-0_65-IPC_A 7680,1140 r270 top value=0Ω
R66 "RC2512JK-070RL" FP-RC2512-0_65-IPC_A 7855,1140 r270 top value=0Ω
R67 "RT0603BRD0720RL" FP-MCR03-IPC_B 6160,1245 r180 top value=20Ω
R68 "RT0603BRD0720RL" FP-MCR03-IPC_B 6160,1177 r180 top value=20Ω
R69 "RT0603FRE07121KL" FP-MCR03-IPC_B 4030,1165 r0 top value=121kΩ
R70 "RT0603BRD0720RL" FP-MCR03-IPC_B 6160,1109 r180 top value=20Ω
R71 "RC0603FR-074K53L" FP-MCR03-IPC_B 4030,1097 r180 top value=4.53kΩ
R72 "RT0603BRD0744K2L" FP-MCR03-IPC_B 4030,1030 r0 top value=44.2kΩ
R73 "RC0603JR-0710RL" FP-MCR03-IPC_B 3770,963 r180 top value=10Ω
R74 "RC0603FR-135K6L" FP-MCR03-IPC_B 4030,963 r180 top value=5.6kΩ
R75 "RT1206FRE072KL" FP-CSR1206-IPC_A 5670,875 r180 top value=2kΩ
R76 "RT0805FRE0720RL" RESC2013X60X35LL10T20 4030,815 r0 top value=20Ω
R77 "RC0603FR-074K99L" FP-MCR03-IPC_B 5660,565 r270 top value=4.99kΩ
R78 "RT0603DRD071KL" FP-MCR03-IPC_B 5732,275 r90 top value=1kΩ
R79 "RT0603DRD071KL" FP-MCR03-IPC_B 5800,275 r90 top value=1kΩ
R80 "RT0603DRD071KL" FP-MCR03-IPC_B 6004,275 r90 top value=1kΩ
R81 "WFC1206R0500FE66" FP-CSR1206-IPC_A 3820,135 r180 top value=50mΩ
R82 "CRCW08051K00JNTA" RESC2013X50X30LL20T20 3910,5130 r270 bottom value=1kΩ
R83 "CRCW08051K00JNTA" RESC2013X50X30LL20T20 3840,5130 r270 bottom value=1kΩ
R84 "CRCW08051K00JNTA" RESC2013X50X30LL20T20 3910,4430 r270 bottom value=1kΩ
R85 "CRCW08051K00JNTA" RESC2013X50X30LL20T20 3840,4430 r270 bottom value=1kΩ
R86 "PHPA1206E6802BST1" RESC3216X65X50NL15T25 5325,3770 r90 bottom value=68kΩ
R87 "CRCW08051K00JNTA" RESC2013X50X30LL20T20 3910,3730 r270 bottom value=1kΩ
R88 "CRCW08051K00JNTA" RESC2013X50X30LL20T20 3840,3730 r270 bottom value=1kΩ
R89 "CRE2512-FZ-R002E-3" FP-RC2512-0_65-MFG 7870,3550 r270 bottom value=2mΩ
R90 "PHPA1206E6802BST1" RESC3216X65X50NL15T25 5325,3615 r90 bottom value=68kΩ
R91 "PHPA1206E6802BST1" RESC3216X65X50NL15T25 5215,3510 r90 bottom value=68kΩ
R92 "PHPA1206E6802BST1" RESC3216X65X50NL15T25 5325,3405 r90 bottom value=68kΩ
R93 "PHPA1206E6802BST1" RESC3216X65X50NL15T25 5215,3300 r90 bottom value=68kΩ
R94 "RT0603DRD071KL" FP-MCR03-IPC_B 5918,3290 r270 bottom value=1kΩ
R95 "RT0603DRD071KL" FP-MCR03-IPC_B 5782,3290 r270 bottom value=1kΩ
R96 "RT0603DRD071KL" FP-MCR03-IPC_B 5714,3290 r90 bottom value=1kΩ
R97 "RC0603JR-0710RL" FP-MCR03-IPC_B 5249,3165 r90 bottom value=10Ω
R98 "RT0603BRD0720RL" FP-MCR03-IPC_B 5113,3165 r90 bottom value=20Ω
R99 "CRE2512-FZ-R002E-3" FP-RC2512-0_65-MFG 7580,3000 r270 bottom value=2mΩ
R100 "RC0603FR-07680RL" FP-MCR03-IPC_B 5595,2756 r180 bottom value=680Ω
R101 "RC0603FR-07680RL" FP-MCR03-IPC_B 5595,2688 r180 bottom value=680Ω
R102 "RC0603FR-07680RL" FP-MCR03-IPC_B 5595,2621 r180 bottom value=680Ω
R103 "RT0805FRE072KL" FP-MCR10-IPC_A 5595,2542 r180 bottom value=2kΩ
R104 "RC0805FR-07499RL" FP-MCR10-IPC_A 5595,2452 r180 bottom value=499Ω
R105 "RMCF1206FT22R0" FP-CSR1206-IPC_A 4280,2360 r90 bottom value=22Ω
R106 "TNPW1206249KBEEA" RESC3216X65X50NL15T25 7265,2410 r180 bottom value=249kΩ
R107 "TNPW1206249KBEEA" RESC3216X65X50NL15T25 7085,2410 r180 bottom value=249kΩ
R108 "TNPW1206249KBEEA" RESC3216X65X50NL15T25 6904.88,2410 r180 bottom value=249kΩ
R109 "TNPW1206249KBEEA" RESC3216X65X50NL15T25 6725,2410 r180 bottom value=249kΩ
R110 "TNPW1206249KBEEA" RESC3216X65X50NL15T25 6545,2410 r180 bottom value=249kΩ
R111 "TNPW1206249KBEEA" RESC3216X65X50NL15T25 6365,2410 r180 bottom value=249kΩ
R112 "RC0805FR-07249RL" FP-MCR10-IPC_A 5595,2363 r180 bottom value=249Ω
R113 "RC0603FR-07100KL" FP-MCR03-IPC_B 5445,2375 r0 bottom value=100kΩ
R114 "RC0603FR-07100KL" FP-MCR03-IPC_B 5320,2375 r180 bottom value=100kΩ
R115 "RC0603FR-07100KL" FP-MCR03-IPC_B 5445,2307 r0 bottom value=100kΩ
R116 "RC0603FR-07100KL" FP-MCR03-IPC_B 5320,2307 r180 bottom value=100kΩ
R117 "RC0603FR-07100KL" FP-MCR03-IPC_B 5445,2240 r0 bottom value=100kΩ
R118 "RC0603FR-07100KL" FP-MCR03-IPC_B 5320,2240 r180 bottom value=100kΩ
R119 "ERJ-PB3B1801V" FP-MCR03-IPC_B 6160,2232 r180 bottom value=1.8kΩ
R120 "TNPW1206249KBEEA" RESC3216X65X50NL15T25 7265,2170 r180 bottom value=249kΩ
R121 "TNPW1206249KBEEA" RESC3216X65X50NL15T25 7085,2170 r180 bottom value=249kΩ
R122 "TNPW1206249KBEEA" RESC3216X65X50NL15T25 6905,2170 r180 bottom value=249kΩ
R123 "TNPW1206249KBEEA" RESC3216X65X50NL15T25 6725,2170 r180 bottom value=249kΩ
R124 "TNPW1206249KBEEA" RESC3216X65X50NL15T25 6545,2170 r180 bottom value=249kΩ
R125 "TNPW1206249KBEEA" RESC3216X65X50NL15T25 6365,2170 r180 bottom value=249kΩ
R126 "RC0603FR-074K99L" FP-MCR03-IPC_B 6160,2164 r180 bottom value=4.99kΩ
R127 "KTR25JZPF8203" RESC3125X70X40LL20T20 1720,2085 r90 bottom value=820kΩ
R128 "KTR25JZPF8203" RESC3125X70X40LL20T20 1900,2000 r0 bottom value=820kΩ
R129 "KTR25JZPF8203" RESC3125X70X40LL20T20 1720,1915 r270 bottom value=820kΩ
R130 "RC0603FR-070RL" FP-MCR03-IPC_B 6160,1816 r0 bottom value=0Ω
R131 "ERJ-PB3B1801V" FP-MCR03-IPC_B 6160,1680 r180 bottom value=1.8kΩ
R132 "RC0603FR-074K99L" FP-MCR03-IPC_B 6160,1611 r180 bottom value=4.99kΩ
R133 "RT0603DRD071KL" FP-MCR03-IPC_B 6040,1502 r270 bottom value=1kΩ
R134 "RC0603FR-07330RL" FP-MCR03-IPC_B 5900,1483 r0 bottom value=330Ω
R135 "RT0603DRD071KL" FP-MCR03-IPC_B 6040,1352 r90 bottom value=1kΩ
R136 "ERJ3EKF1002V" FP-MCR03-IPC_B 3530,1093 r180 bottom value=10kΩ
R137 "ERJ3EKF1002V" FP-MCR03-IPC_B 4030,1090 r180 bottom value=10kΩ
R138 "RT0603BRD0756K2L" FP-MCR03-IPC_B 4030,956 r0 bottom value=56.2kΩ
R139 "RC0603FR-070RL" FP-MCR03-IPC_B 4030,889 r180 bottom value=0Ω
R140 "RT0603FRE07100RL" FP-MCR03-IPC_B 4030,752 r0 bottom value=100Ω
R141 "RT1206DRD07499KL" FP-CSR1206-IPC_A 3870,670 r180 bottom value=499kΩ
R142 "RT1206DRD07499KL" FP-CSR1206-IPC_A 3675,670 r180 bottom value=499kΩ
R143 "RT1206DRD07499KL" FP-CSR1206-IPC_A 3480,670 r180 bottom value=499kΩ
R144 "RC0603JR-07120RL" FP-MCR03-IPC_B 6765,200 r0 bottom value=120Ω
RV1 "550VAC, 745VDC" D23W10.1H27P3.4 313,3338.15 r90 top value=N/A
RV2 "550VAC, 745VDC" D23W10.1H27P3.4 970,3085 r0 top value=N/A
RV3 "550VAC, 745VDC" D23W10.1H27P3.4 1875,3085 r0 top value=N/A
RV4 "SL32 5R020-B" "SL22 10008-B-Footprint-1" 3727.64,1730 r0 top value=5Ω
RV5 "SL32 5R020-B" "SL22 10008-B-Footprint-1" 3727.64,1480 r180 top value=5Ω
T1 "11328-T078" 11328-T078 4900,1240 r0 top locked value=670μH
TP1 "5010" KSTN-5010_V 7100,5985 r0 top value=RED
TP2 "5011" KSTN-5011_V 7420,5985 r0 top value=BLACK
TP3 "5010" KSTN-5010_V 7100,5845 r0 top value=RED
TP4 "5011" KSTN-5011_V 7420,5845 r0 top value=BLACK
TP5 "5012" KSTN-5012_V 7885,4985 r0 top value=WHITE
TP6 "5012" KSTN-5012_V 7885,4585 r0 top value=WHITE
TP7 "5012" KSTN-5012_V 7885,4185 r0 top value=WHITE
TP8 "5010" KSTN-5010_V 4905,2765 r0 top value=RED
TP9 "5011" KSTN-5011_V 4905,2620 r0 top value=BLACK
TP10 "5011" KSTN-5011_V 2890,1615 r0 top value=BLACK
TP11 "5011" KSTN-5011_V 7515,880 r0 top value=BLACK
TP12 "5010" KSTN-5010_V 7515,735 r0 top value=RED
TP13 "5010" KSTN-5010_V 7515,590 r0 top value=RED
U1 "UCC5350SBD" D0008B_HV 4230,6100 r0 top value=N/A
U2 "UCC5350SBD" D0008B_HV 4230,5840 r0 top value=N/A
U3 "UCC5350SBD" D0008B_HV 4230,5580 r0 top value=N/A
U4 "MGJ2D121503SC" MGJ2D121509SC 4245,5232.2 r0 top value=N/A
U5 "UCC5350SBD" D0008B_HV 4230,4880 r0 top value=N/A
U6 "MGJ2D121503SC" MGJ2D121509SC 4245,4530 r0 top value=N/A
U7 "UCC5350SBD" D0008B_HV 4230,4180 r0 top value=N/A
U8 "MGJ2D121503SC" MGJ2D121509SC 4245,3830 r0 top value=N/A
U9 "AMC1303M0520DWVR" DWV0008A 6745,3550 r180 top value=N/A
U10 "UCC5350SBD" D0008B_HV 4230,3480 r0 top value=N/A
U11 "TMDSCNCD280039C" TMDSCNCD280039C 5921.93,2006.77 r270 top locked value=N/A
U12 "MGJ2D121503SC" MGJ2D121509SC 4245,3130 r0 top value=N/A
U13 "AMC1303M0520DWVR" DWV0008A 6745,3140 r180 top value=N/A
U14 "AMC1303M0520DWVR" DWV0008A 5265,2970 r270 top value=N/A
U15 "AMC1303M0520DWVR" DWV0008A 6745,2730 r180 top value=N/A
U16 "R-78E5.0-1.0" CONV_R-78E5.0-1.0 4640,2205 r90 top value=N/A
U17 "SN74LV541ATPWR" PW0020A_L 5560,2135 r180 top value=N/A
U18 "AD8615AUJZ-REEL7" ADI-UJ-5_M 6160,2025 r90 top value=N/A
U19 "AD8615AUJZ-REEL7" ADI-UJ-5_M 6157.4,1463.23 r90 top value=N/A
U20 "ISO1050DUBR" DUB0008A_M 6875,755 r270 top value=N/A
U21 "R-78E3.3-1.0" CONV_R-78E3.3-1.0 6370,755 r90 top value=N/A
U22 "TXB0106PWR" PW0016A_L 5830,510 r270 top value=N/A
U23 "AS78L05RTR-G1" SOT-89_4P5X2P45_DIO 7025,3550 r90 bottom value=N/A
U24 "AS78L05RTR-G1" SOT-89_4P5X2P45_DIO 4970,3175 r180 bottom value=N/A
U25 "AS78L05RTR-G1" SOT-89_4P5X2P45_DIO 7025,3140 r90 bottom value=N/A
U26 "AD8541ARTZ-REEL7" ADI-RJ-5_N 5765,3140 r270 bottom value=N/A
U27 "AS78L05RTR-G1" SOT-89_4P5X2P45_DIO 7025,2730 r90 bottom value=N/A
U28 "AD8615AUJZ-REEL7" ADI-UJ-5_M 6160,2025 r90 bottom value=N/A
U29 "AD8541ARTZ-REEL7" ADI-RJ-5_N 6160,1352 r90 bottom value=N/A
U30 "LT8316EFE#PBF" TSSOP20_FE_BB(16) 3780,975 r0 bottom locked value=N/A
U31 "R1SE-0505-R" FP-R1SE-0505-R-MFG 6885,755 r180 bottom value=N/A

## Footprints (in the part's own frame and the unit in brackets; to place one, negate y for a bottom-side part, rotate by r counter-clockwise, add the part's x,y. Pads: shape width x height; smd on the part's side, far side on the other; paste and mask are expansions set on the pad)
94DN-02000-A-200 [mm]
  round 11 hole 4.5: 1(-95.25,55.5) 2(95.25,55.5) 3(-95.25,-55.5) 4(95.25,-55.5)
  body extent -99.97,-61.51 100.03,61.49, height 52
11328-T078 [mm] "Sumida 11328-T078 Flyback transformer"
  round 2.2 hole 1.1: 1(-12.7,11.43) 2(-12.7,7.62) 3(-12.7,3.81) 4(-12.7,-3.81) 5(-12.7,-7.62) 6(-12.7,-11.43) 7(12.7,-11.43) 8(12.7,-7.62) 9(12.7,-3.81) 10(12.7,3.81) 11(12.7,7.62) 12(12.7,11.43)
  silkscreen extent -16.51,-15 16.5,15, body extent -15,-13.65 14.5,13.65, height 20.52
1777545 [mm]
  round 2.316 hole 1.3: 1(-3.175,4.5) 2(3.175,-4.5)
  silkscreen extent -6.35,-9.25 6.35,6.6, body extent -6.35,-9.25 6.35,6.6, height 27.7
1777561 [mm]
  round 2.316 hole 1.3: 1(-9.525,4.5) 2(-3.175,-4.5) 3(3.175,4.5) 4(9.525,-4.5)
  silkscreen extent -12.7,-9.25 12.7,6.6, body extent -12.7,-9.25 12.7,6.6, height 27.7
61300311121 [mm] "Pin Header, pitch 2.54 mm, THT, Vertical, single row, 3p"
  rect 1.6x1.6 hole 1.1: 1(-2.54,0)
  round 1.6 hole 1.1: 2(0,0) 3(2.54,0)
  silkscreen extent -3.96,-1.35 3.96,1.35, body extent -3.81,-1.27 3.81,1.27, height 8.57
61300511121 [mm] "Pin Header, pitch 2.54 mm, THT, Vertical, single row, 5p"
  rect 1.6x1.6 hole 1.1: 1(-5.08,0)
  round 1.6 hole 1.1: 2(-2.54,0) 3(0,0) 4(2.54,0) 5(5.08,0)
  silkscreen extent -6.5,-1.35 6.5,1.35, body extent -6.35,-1.27 6.35,1.27, height 8.57
696106003002 [mm] "FUSEHOLDER BLOCKS - PCB - CLIP COVER - THT"
  round 2.25 hole 1.5: 1(-7.5,0) 2(7.5,0)
  silkscreen extent -12.2,-4.7 12.2,4.7, body extent -12.2,-4.7 12.2,4.7, height 14.05
ADI-RJ-5_N [mm] "SOT-23, 5-Leads, Body 2.9x1.6mm, Pitch 0.95mm, IPC Medium Density"
  rect 1.1x0.6 smd: 1(-1.2,0.95) 2(-1.2,0) 3(-1.2,-0.95) 4(1.2,-0.95) 5(1.2,0.95)
  silkscreen extent -1.32,-1.5 0.25,1.92, body extent -0.85,-1.5 0.85,1.5, height 1.45
ADI-UJ-5_M [mm] "SOT23, 5-Leads, Body 2.9x1.6mm, Pitch 0.95mm, IPC Low Density"
  rect 1.15x0.7 smd: 1(-1.225,0.95) 2(-1.225,0) 3(-1.225,-0.95) 4(1.225,-0.95) 5(1.225,0.95)
  silkscreen extent -1.35,-1.45 0.25,1.97, body extent -0.8,-1.45 0.8,1.45, height 1
B43630A9128M000 [mm] "400V 1200uF"
  round 3 hole 2: 1(-5,0) 2(5,0)
  silkscreen extent -19.5,-19.5 19.5,19.5, body extent -25.46,-25.46 25.46,25.46, height 82.55
CAP_LDE_QD_1220_KEM [mil]
  rect 49x213 smd paste+0 mask+0: 1(-113.5,0) 2(113.5,0)
  silkscreen extent -77,-112 77,112, body extent -124,-106 124,106, height 79
CAP_MY5UCR_VIS [mil]
  rect 103x159 smd paste+0 mask+0: 1(-254,0) 2(254,0)
  silkscreen extent -240,-176 240,176, body extent -291,-171 291,171, height 45
CONV_R-78E3.3-1.0 [mm]
  rect 1.508x1.508 hole 1: 1(-2.54,-2.25)
  round 1.508 hole 1: 2(0,-2.25) 3(2.54,-2.25)
  silkscreen extent -6.5,-4.25 5.75,4.25, body extent -5.8,-4.25 5.8,4.25, height 9.9
CONV_R-78E5.0-1.0 [mm]
  rect 1.508x1.508 hole 1: 1(-2.54,-2.25)
  round 1.508 hole 1: 2(0,-2.25) 3(2.54,-2.25)
  silkscreen extent -6.5,-4.25 5.75,4.25, body extent -5.8,-4.25 5.8,4.25, height 9.9
D0008B_HV [mm]
  rect 1.4x0.6 smd paste+0 mask+0: 1(-2.75,1.905) 2(-2.75,0.635) 3(-2.75,-0.635) 4(-2.75,-1.905) 5(2.75,-1.905) 6(2.75,-0.635) 7(2.75,0.635) 8(2.75,1.905)
  silkscreen extent -3.3,-2.5 0.9,3.35, body extent -3.01,-2.45 3.01,2.45, height 1.63
D23W10.1H27P3.4 [mm] "Disk Varistor, Diameter 23mm, Width 10.1mm"
  round 1.65 hole 1.1: 1(-5,1.7) 2(5,-1.7)
  silkscreen extent -11.5,-5.05 11.5,5.05, body extent -10.7,-3.65 10.7,3.65, height 24
DIOD-SOD323-2-A_V [mm] "SOD-323, 2-Leads, Body 1.7x1.3mm"
  rect 0.59x0.45 smd: 1(-1.055,0) 2(1.055,0)
  silkscreen extent -0.85,-0.65 1.85,0.65, body extent -0.85,-0.65 0.85,0.65, height 1.2
DIODE_SOD-523_1P2XP8_CNS [mil]
  rect 24x14 smd paste+0 mask+0: 1(-31.5,0) 2(31.5,0)
  silkscreen extent -28,-21 28,21, body extent -36,-16 36,16, height 31
DUB0008A_M [mm] "SOP, 8-Leads, Body 6.7x9.6mm, Pitch 2.54mm, IPC Low Density"
  rrect14% 2.55x0.7 smd: 1(-4.625,3.81) 2(-4.625,1.27) 3(-4.625,-1.27) 4(-4.625,-3.81) 5(4.625,-3.81) 6(4.625,-1.27) 7(4.625,1.27) 8(4.625,3.81)
  silkscreen extent -4.75,-4.8 2.95,4.84, body extent -5.24,-4.75 5.24,4.75, height 4.85
DWV0008A [mm]
  rect 1.8x0.6 smd paste+0 mask+0.051: 1(-5.45,1.905) 2(-5.45,0.635) 3(-5.45,-0.635) 4(-5.45,-1.905) 5(5.45,-1.905) 6(5.45,-0.635) 7(5.45,0.635) 8(5.45,1.905)
  silkscreen extent -6.25,-2.95 2.98,3.35, body extent -5.77,-2.92 5.77,2.93, height 2.72
FM3_SIX-PACK_3PHASE_CRW [mm]
  round 1.524 hole 1.1: DC+_1(-6.4,-6.4) DC+_2(3.2,-6.4) DC+_3(12.8,-6.4) DC-1(-16,0) DC-2(3.2,0) DC-3(16,0) G1(-12.8,-12.8) G2(-16,12.8) G3(-3.2,-12.8) G4(3.2,12.8) G5(6.4,-12.8) G6(16,12.8) NTC1(12.8,-12.8) NTC2(16,-12.8) S1(-16,-12.8) S2(-12.8,12.8) S3(-6.4,-12.8) S4(0,12.8) S5(3.2,-12.8) S6(12.8,12.8) U(-16,6.4) V(3.2,6.4) W(16,6.4)
  round 0 hole 9 unplated: MH1(-26.5,0) MH2(26.5,0)
  Bottom Layer keep-out circle w0.254: c-16,12.8 r5
  Bottom Layer keep-out circle w0.254: c-12.8,12.8 r5
  Bottom Layer keep-out circle w0.254: c0,12.8 r5
  Bottom Layer keep-out circle w0.254: c3.2,12.8 r5
  Bottom Layer keep-out circle w0.254: c12.8,12.8 r5
  Bottom Layer keep-out circle w0.254: c16,12.8 r5
  Bottom Layer keep-out circle w0.254: c16,-12.8 r5
  Bottom Layer keep-out circle w0.254: c12.997,-12.859 r5
  Bottom Layer keep-out circle w0.254: c6.4,-12.8 r5
  Bottom Layer keep-out circle w0.254: c3.2,-12.8 r5
  Bottom Layer keep-out circle w0.254: c-3.2,-12.8 r5
  Bottom Layer keep-out circle w0.254: c-6.4,-12.8 r5
  Bottom Layer keep-out circle w0.254: c-12.8,-12.8 r5
  Bottom Layer keep-out circle w0.254: c-16,-12.8 r5
  silkscreen extent -31.52,-16.88 31.52,16.88, body extent -31.4,-16.9 31.4,16.9, height 11.98
FP-425AB-MFG [mm]
  rect 1.2x1.4 smd paste+0 mask+0: 1(-1.55,0) 2(1.55,0)
  silkscreen extent -2.85,-0.95 0.58,0.95, body extent -1.8,-0.9 1.8,0.9, height 1.43
FP-73415-1471-MFG [mm]
  rect 1.34x1.34 hole 0.84 paste-1000 mask+0: 1(0.01,0)
  round 1.34 hole 0.84 paste-1000 mask+0: 2(-1.27,1.27) 3(1.27,1.27) 4(-1.27,-1.27) 5(1.27,-1.27)
  silkscreen extent -2.54,-1.82 1.82,1.82, body extent -2.04,-2.04 2.04,2.04, height 0.25
FP-APTR3216SECK-MFG [mm]
  rect 1.5x1.6 smd paste+0 mask+0: 1(-1.8,0) 2(1.8,0)
  silkscreen extent -3.3,-1.4 1.9,1.4, body extent -1.6,-0.8 1.6,0.8, height 1.1
FP-C0603C-CF-IPC_B [mil]
  rect 39.63x37.73 smd paste+0 mask+0: 1(-28.58,0) 2(28.58,0)
  silkscreen extent -48,-35 48,35, body extent -58,-29 58,29, height 10
FP-C0603C-CF-MFG [mm]
  rect 0.75x0.9 smd paste+0 mask+0: 1(-0.6,0) 2(0.6,0)
  silkscreen extent -0.87,-0.85 0.88,0.85, body extent -0.8,-0.4 0.8,0.4, height 0.87
FP-C3216-160-0_2-IPC_C [mil]
  rect 61.18x67.17 smd paste+0 mask+0: 1(-42.37,0) 2(42.37,0)
  silkscreen extent -73,-51 73,51, body extent -77,-39 77,39, height 10
FP-C5750-250-0_4-IPC_A [mm]
  rect 1.153x5.503 smd paste+0 mask+0: 1(-3.025,0) 2(3.025,0)
  silkscreen extent -2.07,-2.5 2.07,2.5, body extent -2.85,-2.5 2.85,2.5, height 2.81
FP-CL21-IPC_C [mil]
  rect 41.52x53.39 smd paste+0 mask+0: 1(-28.57,0) 2(28.57,0)
  silkscreen extent -49,-44 49,44, body extent -39,-25 39,25, height 57
FP-CL31-IPC_B [mil]
  rect 51.4x69.22 smd paste+0 mask+0: 1(-54.19,0) 2(54.19,0)
  silkscreen extent -17,-35 17,35, body extent -63,-31 63,31, height 55
FP-CRGP2512-IPC_C [mil]
  rect 37.72x130.17 smd paste+0 mask+0: 1(-114.25,0) 2(114.25,0)
  silkscreen extent -84,-67 84,67, body extent -137,-71 137,71, height 10
FP-CSR1206-IPC_A [mil]
  rect 53.38x71.19 smd paste+0 mask+0: 1(-58.12,0) 2(58.12,0)
  silkscreen extent -20,-36 20,36, body extent -104,-55 104,55, height 10
FP-EEH-G-MFG [mm]
  rect 4.1x2 smd paste+0 mask+0: 1(-4.35,0) 2(4.35,0)
  silkscreen extent -7.12,-5.25 5.25,5.25, body extent -5.85,-5.15 5.85,5.15, height 10.51
FP-GCM188-0_1-IPC_A [mil]
  rect 45.62x39.85 smd paste+0 mask+0: 1(-32.55,0) 2(32.55,0)
  silkscreen extent -55,-36 55,36, body extent -31,-16 31,16, height 35
FP-LTST-C171GKT-MFG [mm]
  rect 1.2x1.2 smd paste+0 mask+0: 1(-1.05,0) 2(1.05,0)
  silkscreen extent -2.37,-1.05 1.05,1.05, body extent -1.75,-0.77 1.75,0.77, height 0.25
FP-LTST-C171GKT-MFG-RED [mm]
  rect 1.2x1.2 smd paste+0 mask+0: 1(-1.05,0) 2(1.05,0)
  silkscreen extent -2.37,-1.05 1.05,1.05, body extent -1,-0.63 1,0.63, height 0.8
FP-LTST-C171GKT-MFG-YELLOW [mm]
  rect 1.2x1.2 smd paste+0 mask+0: 1(-1.05,0) 2(1.05,0)
  silkscreen extent -2.37,-1.05 1.05,1.05, body extent -1,-0.63 1,0.63, height 0.8
FP-MCR03-IPC_B [mil]
  rect 37.72x35.91 smd paste+0 mask+0: 1(-28.62,0) 2(28.62,0)
  silkscreen extent -47,-34 47,34, body extent -57,-28 57,28, height 10
FP-MCR10-IPC_A [mil]
  rect 49.53x57.56 smd paste+0 mask+0: 1(-38.46,0) 2(38.46,0)
  silkscreen extent -63,-45 63,45, body extent -39,-25 39,25, height 26
FP-R1SE-0505-R-MFG [mm]
  rect 1.8x1.2 smd paste+0 mask+0: 1(-5.1,3.81) 2(-5.1,1.27) 4(-5.1,-3.81) 5(5.1,-3.81) 8(5.1,3.81)
  silkscreen extent -6.78,-6.5 5.35,6.5, body extent -5.55,-6.38 5.55,6.37, height 7
FP-RC2512-0_65-IPC_A [mil]
  rect 53.47x132.21 smd paste+0 mask+0: 1(-122.13,0) 2(122.13,0)
  silkscreen extent -84,-66 84,66, body extent -169,-86 169,86, height 10
FP-RC2512-0_65-MFG [mm]
  rect 1.8x4 smd paste+0 mask+0: 1(-3.1,0) 2(3.1,0)
  silkscreen extent -1.83,-1.63 1.83,1.63, body extent -4.1,-2.1 4.1,2.1, height 0.25
FP-SMA-MFG [mm]
  rect 1.7x1.68 smd paste+0 mask+0: 1(-1.79,0) 2(1.79,0)
  silkscreen extent -2.25,-1.4 2.25,1.4, body extent -2.55,-1.33 2.55,1.33, height 2.29
FP-T9GV1L14-12-MFG [mm]
  rect 3.2x3.2 hole 2.1 paste-1000 mask+0: 1(8.51,4.78)
  round 3.2 hole 2.1 paste-1000 mask+0: 2(-9.27,2.24)
  round 1.7 hole 1.1 paste-1000 mask+0: 3(-5.46,-10.46) 4(4.7,-10.46)
  silkscreen extent -10.75,-14.5 11.6,14.5, body extent -10.97,-14.6 10.85,14.6, height 0.25
FP-TO-263-7-MFG [mm]
  rect 0.9x3.4 smd paste+0 mask+0: 1(-3.81,-6.764) 2(-2.54,-6.764) 3(-1.27,-6.764) 4(0,-6.764) 5(1.27,-6.764) 6(2.54,-6.764) 7(3.81,-6.764)
  round 4.505 smd paste+0 mask+0: 8(-2.737,4.429)
  Top Layer region: -5.24,1.926 -5.24,8.464 -1.65,8.464 -1.65,6.746 1.65,6.746 1.65,8.464 5.24,8.464 5.24,1.926
  silkscreen extent -5.12,-9.14 5.12,1.55, body extent -5.09,-8.47 5.1,8.18, height 4.54
FP-VY1470-MFG [mm]
  rect 1.3x1.3 hole 0.8 paste-1000 mask+0: 1(-5,0)
  round 1.3 hole 0.8 paste-1000 mask+0: 2(5,0)
  silkscreen extent -6,-2.5 6,2.5, body extent -6.1,-2.6 6.1,2.6, height 0.25
KSTN-5010_V [mm] "Test Point, Dia 3.17mm"
  round 2.1 hole 1.6: 1(0,0)
  silkscreen extent -1.59,-1.58 1.59,1.58, body extent -1.59,-1.59 1.59,1.59, height 8.13
KSTN-5011_V [mm] "Test Point, Dia 3.17mm"
  round 2.1 hole 1.6: 1(0,0)
  silkscreen extent -1.59,-1.58 1.59,1.58, body extent -1.59,-1.59 1.59,1.59, height 8.13
KSTN-5012_V [mm] "Test Point, Dia 3.17mm"
  round 2.1 hole 1.6: 1(0,0)
  silkscreen extent -1.59,-1.58 1.59,1.58, body extent -1.59,-1.59 1.59,1.59, height 8.13
L717SDE09PA4CH4RC309 [mm] "CONN D-SUB PLUG 9POS R/A SLDR"
  round 1.508 hole 1: 1(-5.54,1.42) 2(-2.77,1.42) 3(0,1.42) 4(2.77,1.42) 5(5.54,1.42) 6(-4.155,-1.42) 7(-1.385,-1.42) 8(1.385,-1.42) 9(4.155,-1.42)
  round 4.066 hole 3.05: 10(-12.495,0) 11(12.495,0)
  silkscreen extent -15.7,-8.5 15.7,3.4, body extent -15.4,-15.6 15.41,3, height 12.55
MGJ2D121509SC [mm]
  round 1.725 hole 1.15: 1(-7.62,2.23) 2(-5.08,2.23) 5(2.54,2.23) 6(5.08,2.23) 7(7.62,2.23)
  silkscreen extent -10.52,-4.9 9.75,4.9, body extent -9.9,-5.09 9.6,4.73, height 13.09
MH_M4_P [mm] "M4 plated mounting hole"
  round 11 hole 4.5: 1(0,0)
  body extent -4,-4.62 4,4.62, height 102.05
PW0016A_L [mm] "SOP, 16-Leads, Body 5.1x4.5mm, Pitch 0.65mm, IPC High Density"
  rrect25% 1.2x0.4 smd: 1(-2.85,2.275) 2(-2.85,1.625) 3(-2.85,0.975) 4(-2.85,0.325) 5(-2.85,-0.325) 6(-2.85,-0.975) 7(-2.85,-1.625) 8(-2.85,-2.275) 9(2.85,-2.275) 10(2.85,-1.625) 11(2.85,-0.975) 12(2.85,-0.325) 13(2.85,0.325) 14(2.85,0.975) 15(2.85,1.625) 16(2.85,2.275)
  silkscreen extent -2.97,-2.55 1.85,3.15, body extent -3.21,-2.5 3.21,2.5, height 1
PW0020A_L [mm] "SOP, 20-Leads, Body 6.6x4.5mm, Pitch 0.65mm, IPC High Density"
  rrect25% 1.2x0.4 smd: 1(-2.85,2.925) 2(-2.85,2.275) 3(-2.85,1.625) 4(-2.85,0.975) 5(-2.85,0.325) 6(-2.85,-0.325) 7(-2.85,-0.975) 8(-2.85,-1.625) 9(-2.85,-2.275) 10(-2.85,-2.925) 11(2.85,-2.925) 12(2.85,-2.275) 13(2.85,-1.625) 14(2.85,-0.975) 15(2.85,-0.325) 16(2.85,0.325) 17(2.85,0.975) 18(2.85,1.625) 19(2.85,2.275) 20(2.85,2.925)
  silkscreen extent -2.98,-3.3 1.85,3.8, body extent -3.21,-3.25 3.21,3.25, height 1
RESC2013X50X30LL20T20 [mm] "Chip Resistor, 2-Leads, Body 2.00x1.25mm, IPC High Density"
  rect 0.85x1.35 smd: 1(-0.825,0) 2(0.825,0)
  silkscreen extent -0.1,-0.58 0.1,0.58, body extent -1.1,-0.72 1.1,0.72, height 0.5
RESC2013X60X35LL10T20 [mm] "Chip Resistor, 2-Leads, Body 2.00x1.25mm, IPC High Density"
  rect 0.8x1.25 smd: 1(-0.8,0) 2(0.8,0)
  silkscreen extent -0.1,-0.53 0.1,0.53, body extent -1.05,-0.67 1.05,0.67, height 0.6
RESC3125X70X40LL20T20 [mm] "Chip Resistor, 2-Leads, Body 3.10x2.50mm, IPC High Density"
  rect 0.95x2.6 smd: 1(-1.325,0) 2(1.325,0)
  silkscreen extent -0.45,-1.2 0.45,1.2, body extent -1.65,-1.35 1.65,1.35, height 0.7
RESC3125X70X40NL20T20 [mm] "Chip Resistor, 2-Leads, Body 3.10x2.50mm, IPC Medium Density"
  rect 1.15x2.7 smd: 1(-1.425,0) 2(1.425,0)
  silkscreen extent -0.45,-1.25 0.45,1.25, body extent -1.65,-1.35 1.65,1.35, height 0.7
RESC3216X65X50NL15T25 [mm] "Chip Resistor, 2-Leads, Body 3.20x1.60mm, IPC Medium Density"
  rect 1.25x1.75 smd: 1(-1.4,0) 2(1.4,0)
  silkscreen extent -0.4,-0.77 0.4,0.77, body extent -1.68,-0.87 1.68,0.87, height 0.65
SBR2512W [mm] "3P diode bridge 1200V 25A"
  round 3.81 hole 1.85: 1(-9.65,9.65) 2(2.649,9.65) 3(-2.649,-9.65) 4(-9.65,-9.65) 5(9.65,9.65)
  round 0 hole 10 unplated: 6(0,0)
  body extent -14.27,-14.23 14.23,14.27
"SL22 10008-B-Footprint-1" [mil]
  round 70 hole 45: 1(-147.64,74.41) 2(147.64,-74.41)
  silkscreen extent -433,-118 433,118, body extent -433,-118 433,118, height 1024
